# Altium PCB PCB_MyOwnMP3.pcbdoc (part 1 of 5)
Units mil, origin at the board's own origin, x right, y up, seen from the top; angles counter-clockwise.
Board outline 3605 x 4860 mil, 6 copper layers (Top Layer, Inner1, Inner2, Inner3, Inner4, Bottom Layer); 291 components, 261 nets, 1070 pads, 1658 vias.
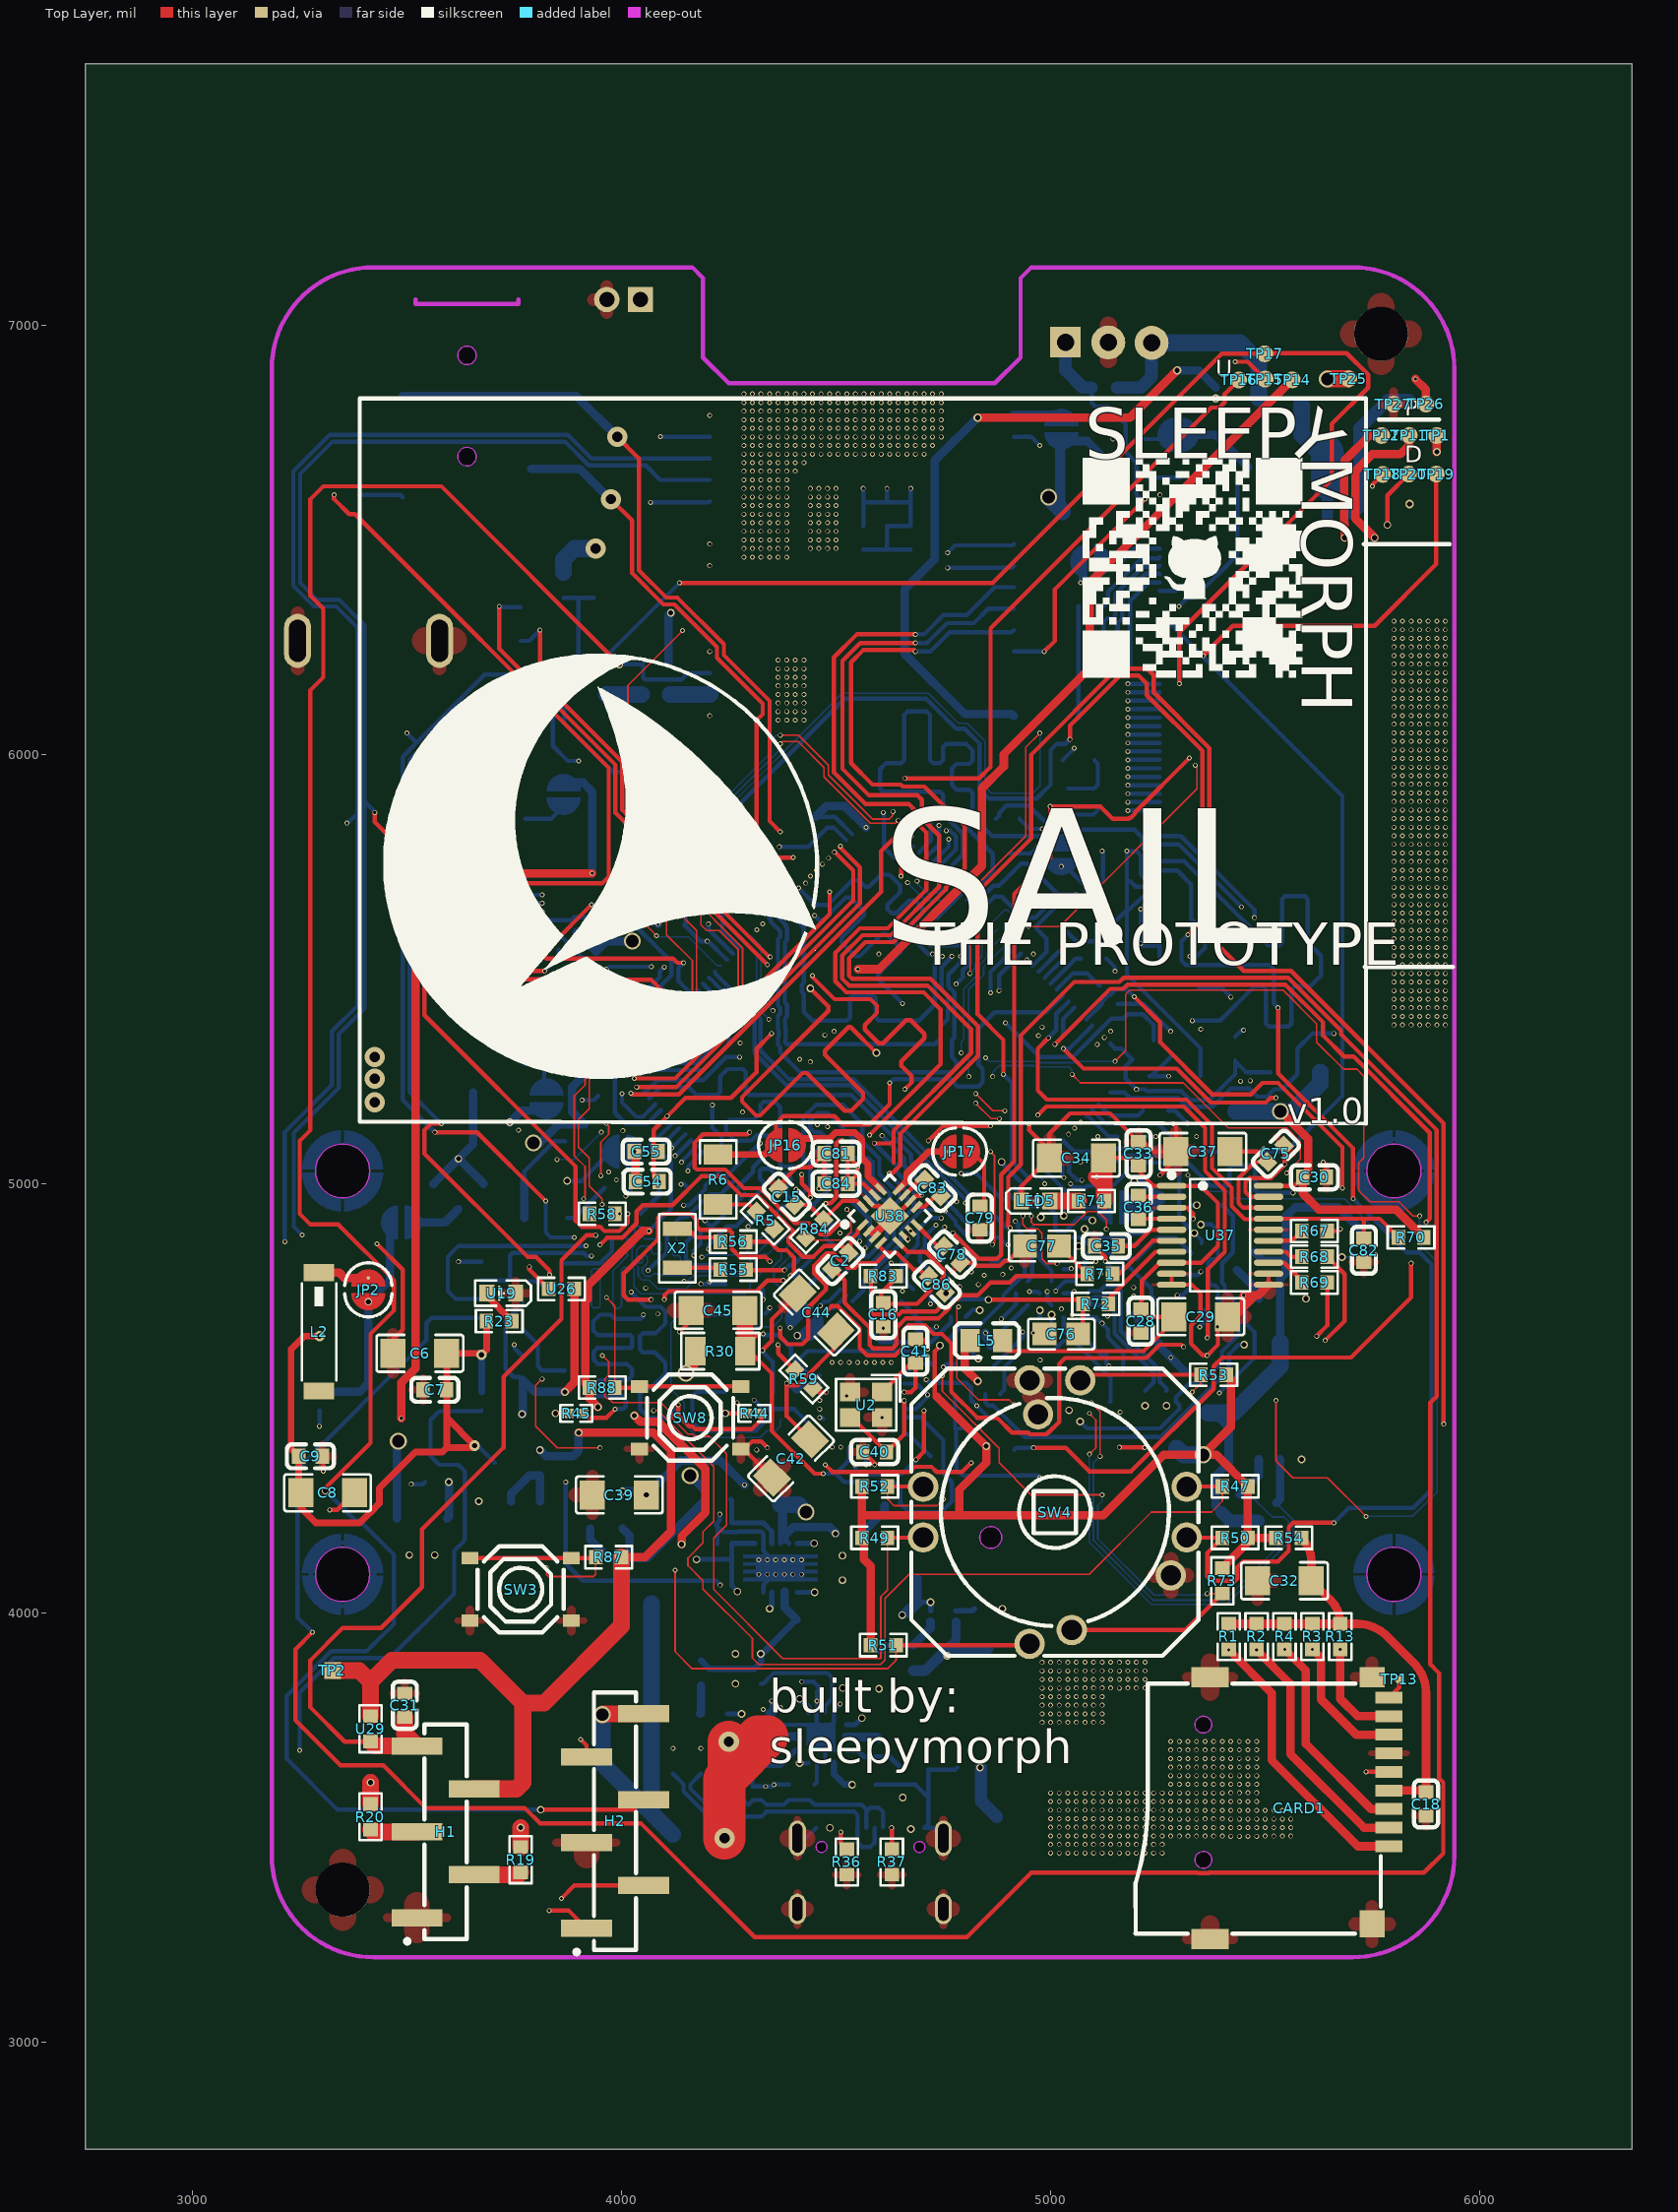
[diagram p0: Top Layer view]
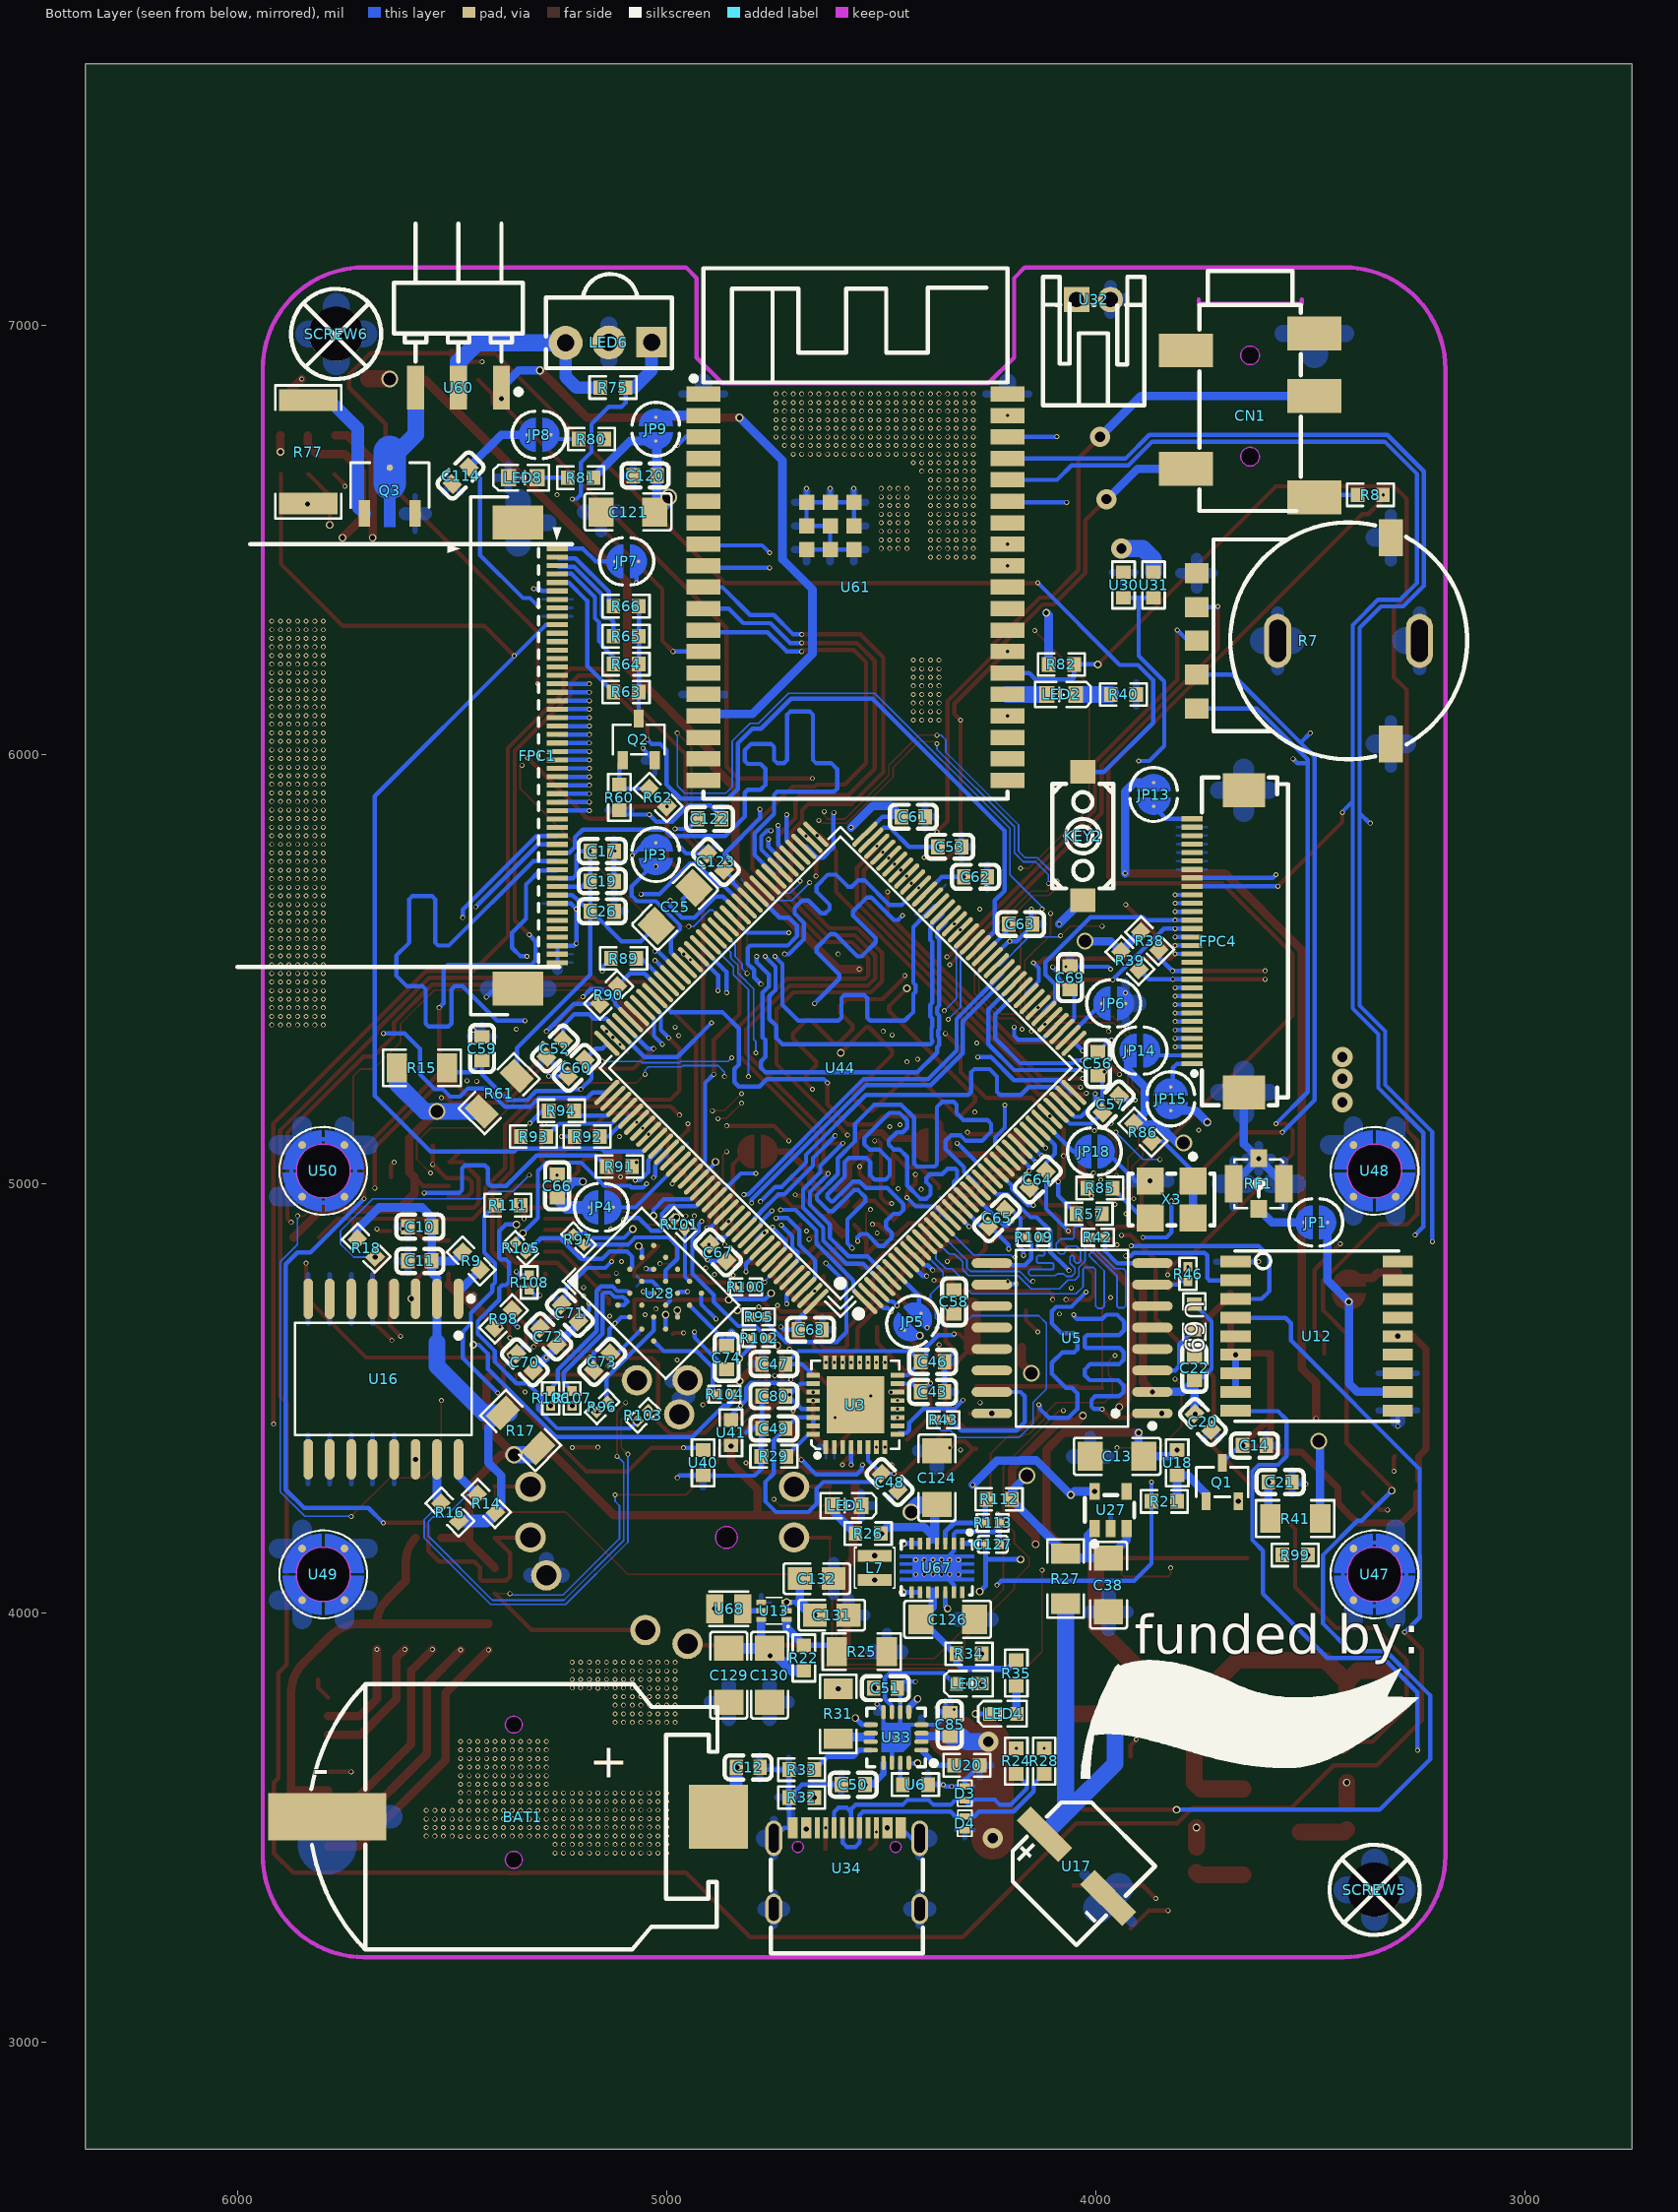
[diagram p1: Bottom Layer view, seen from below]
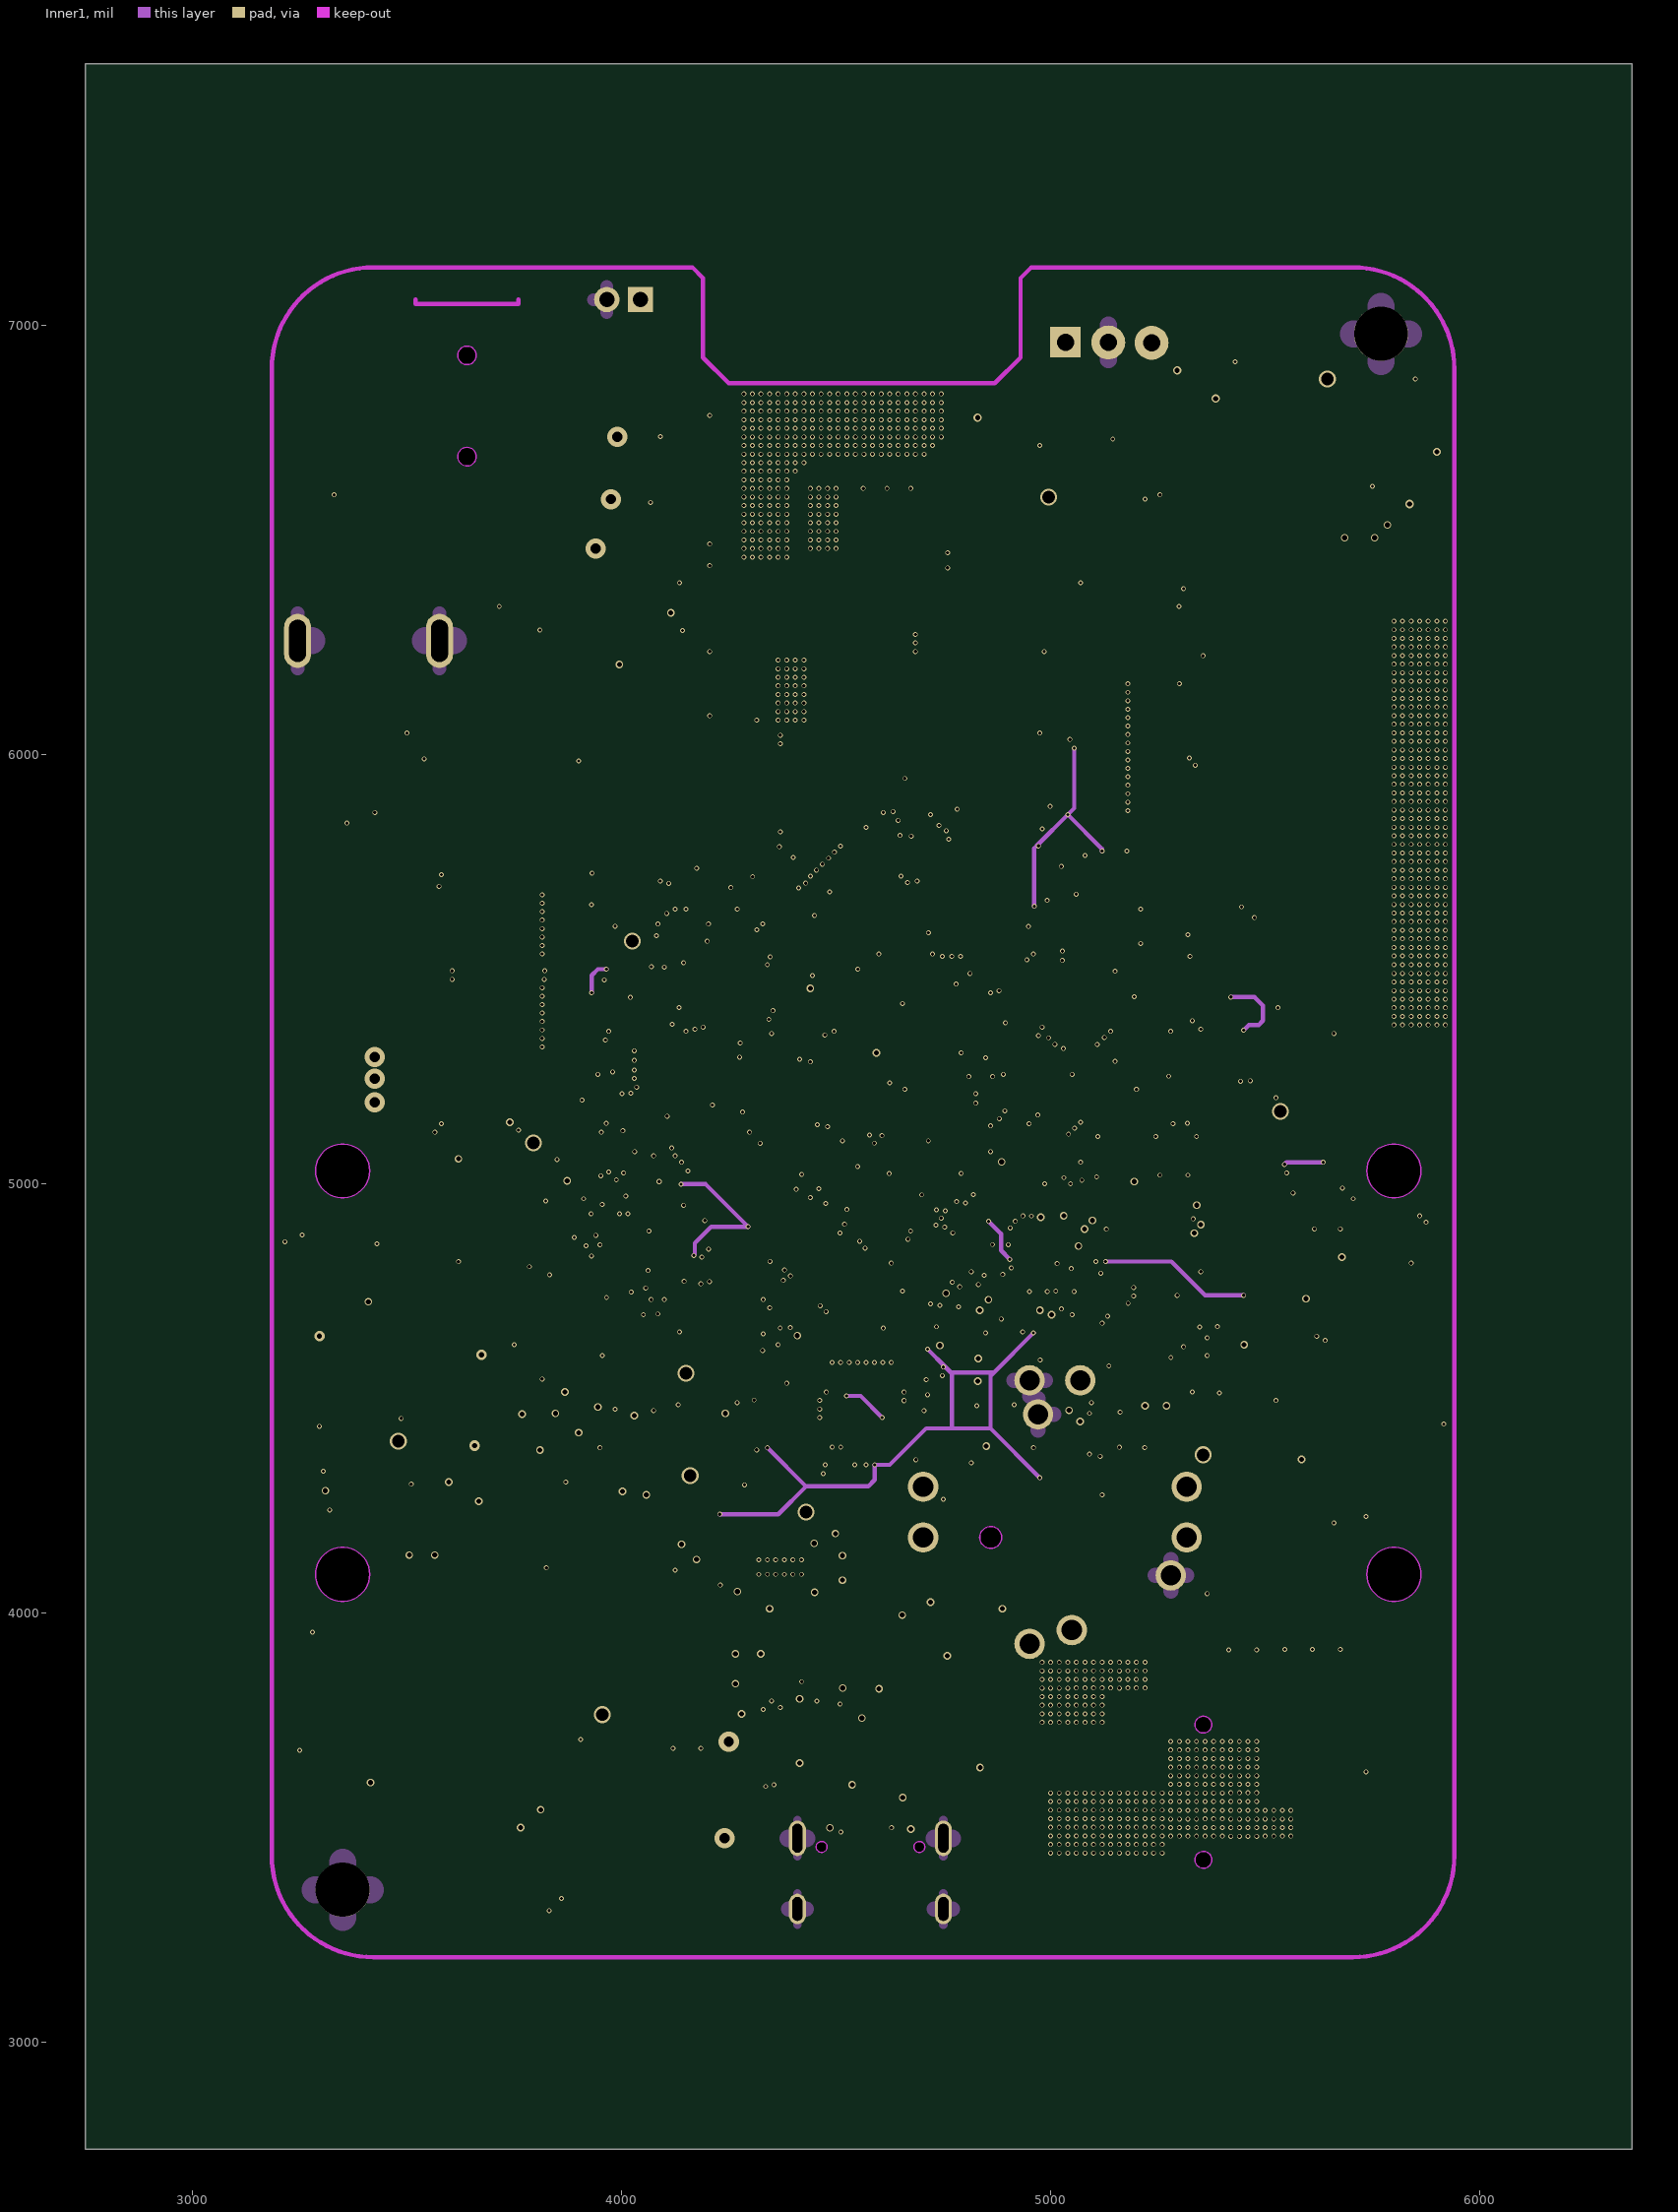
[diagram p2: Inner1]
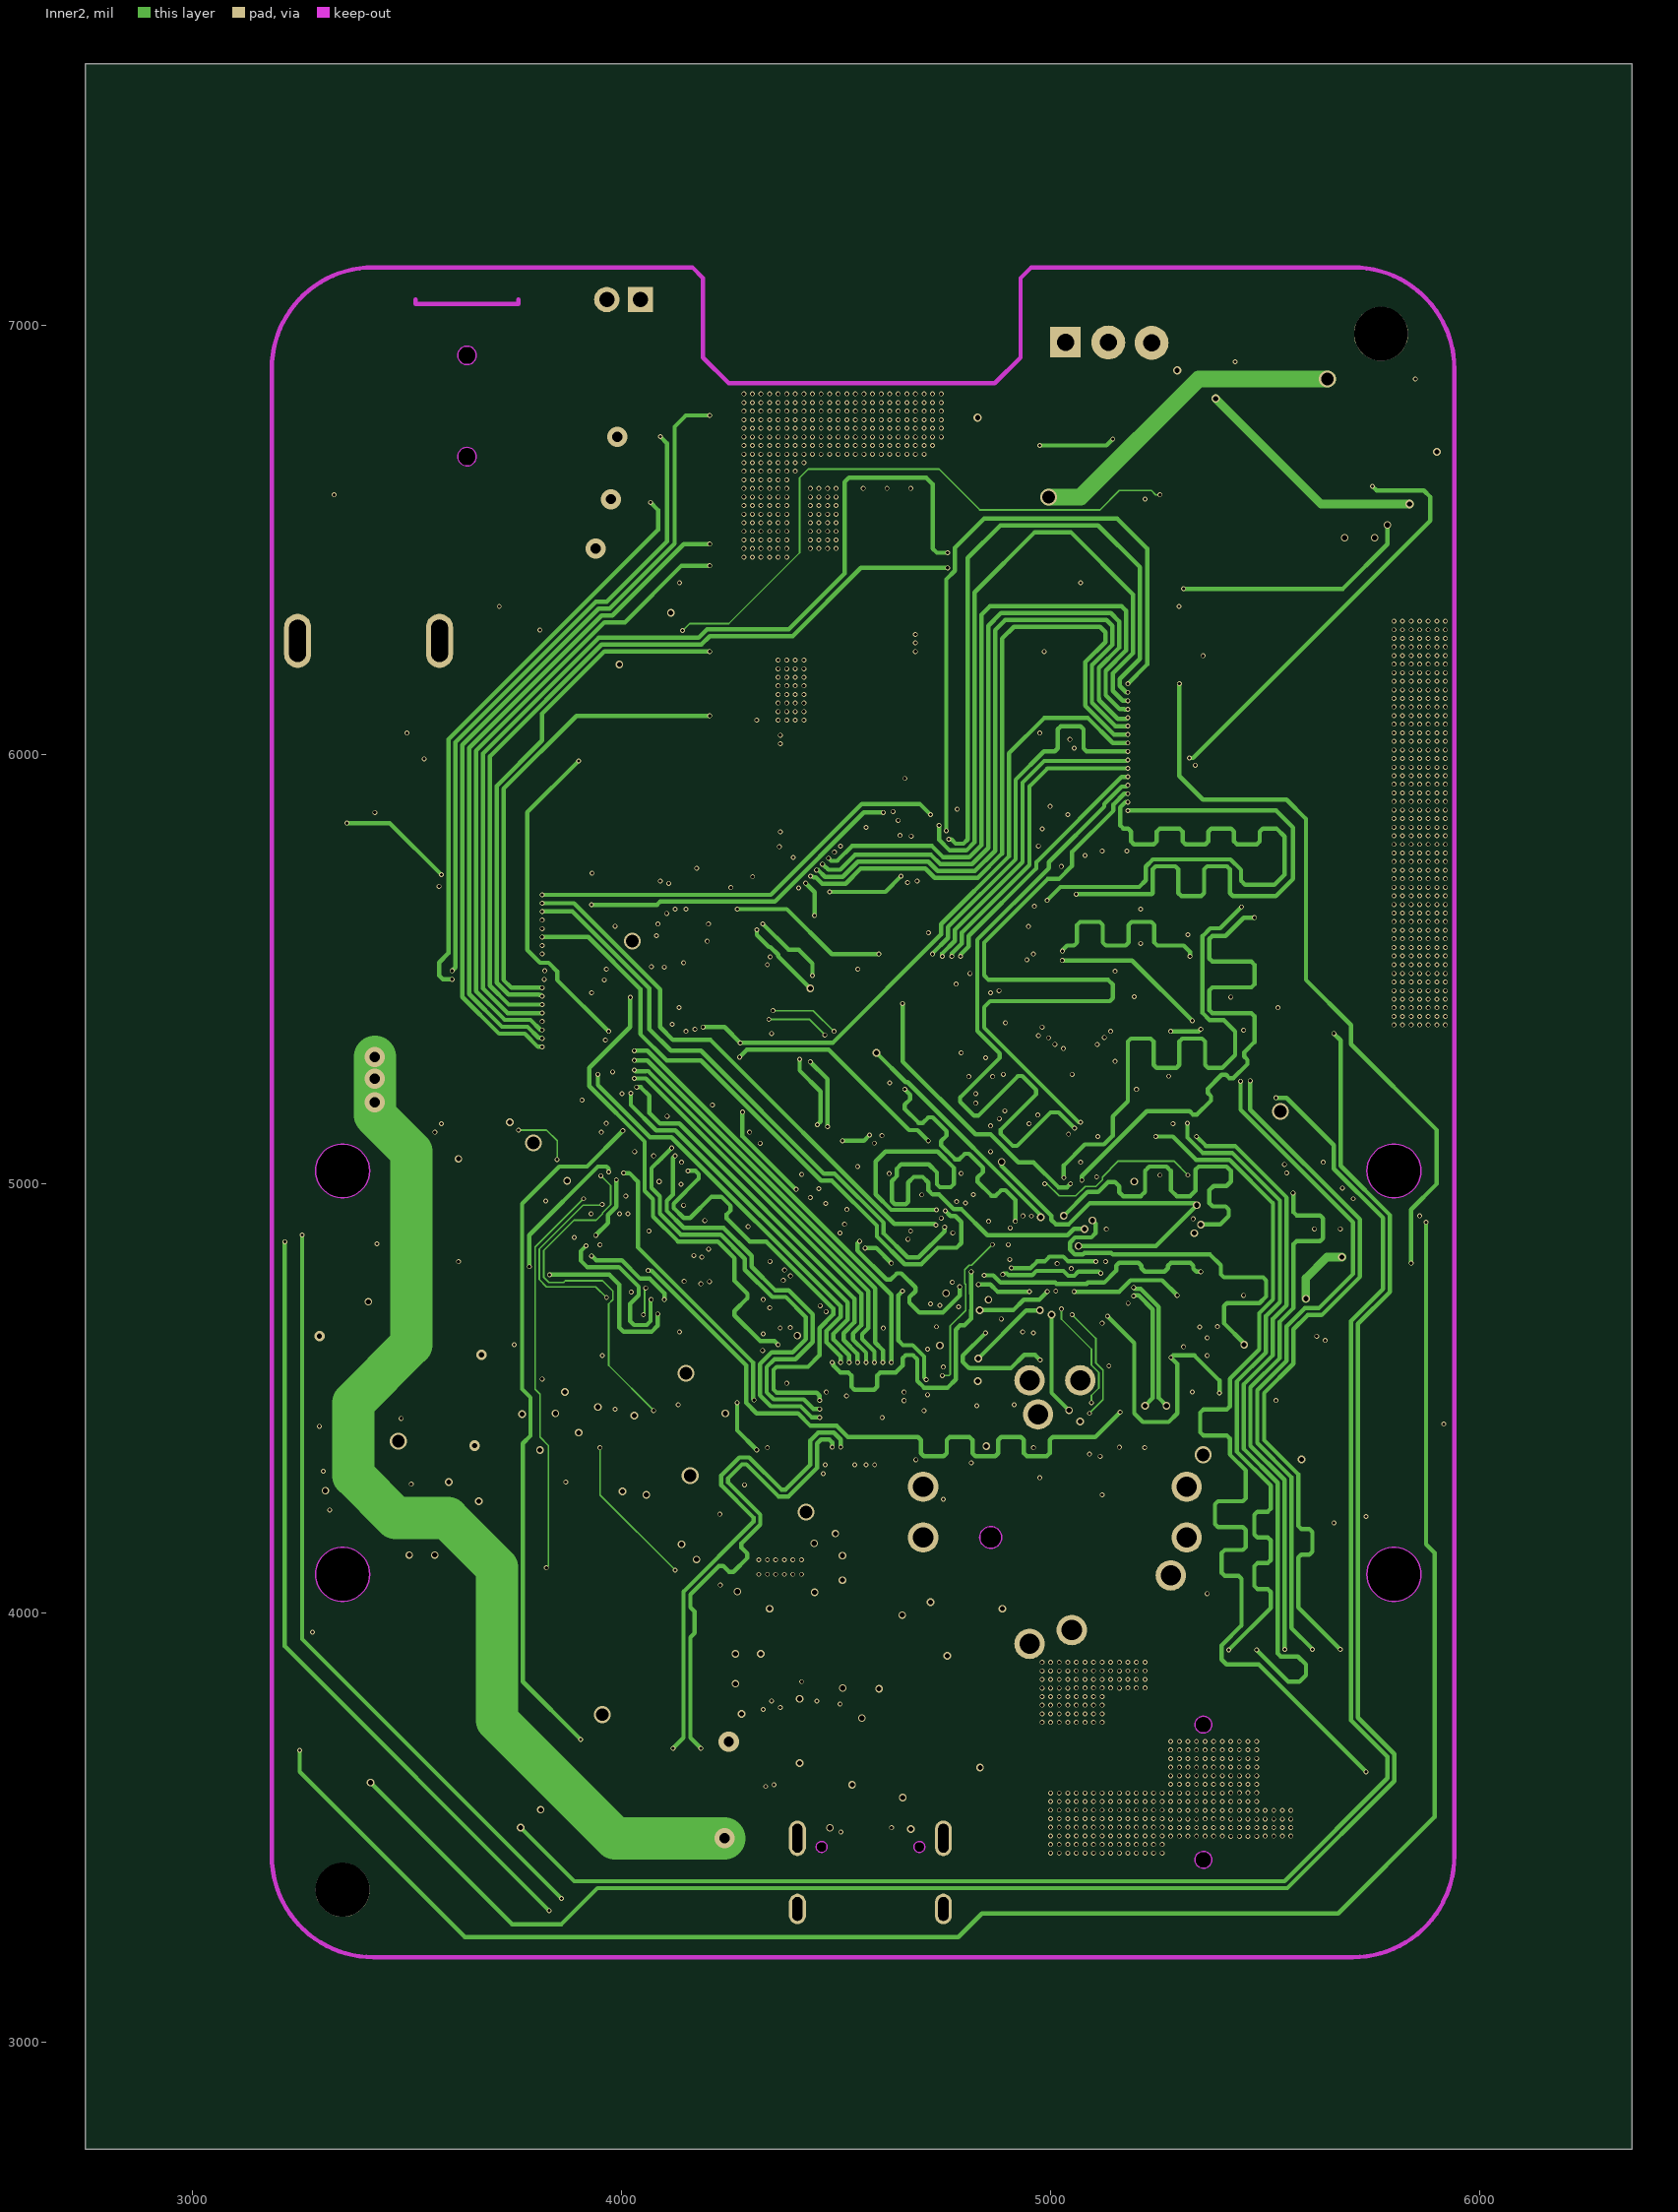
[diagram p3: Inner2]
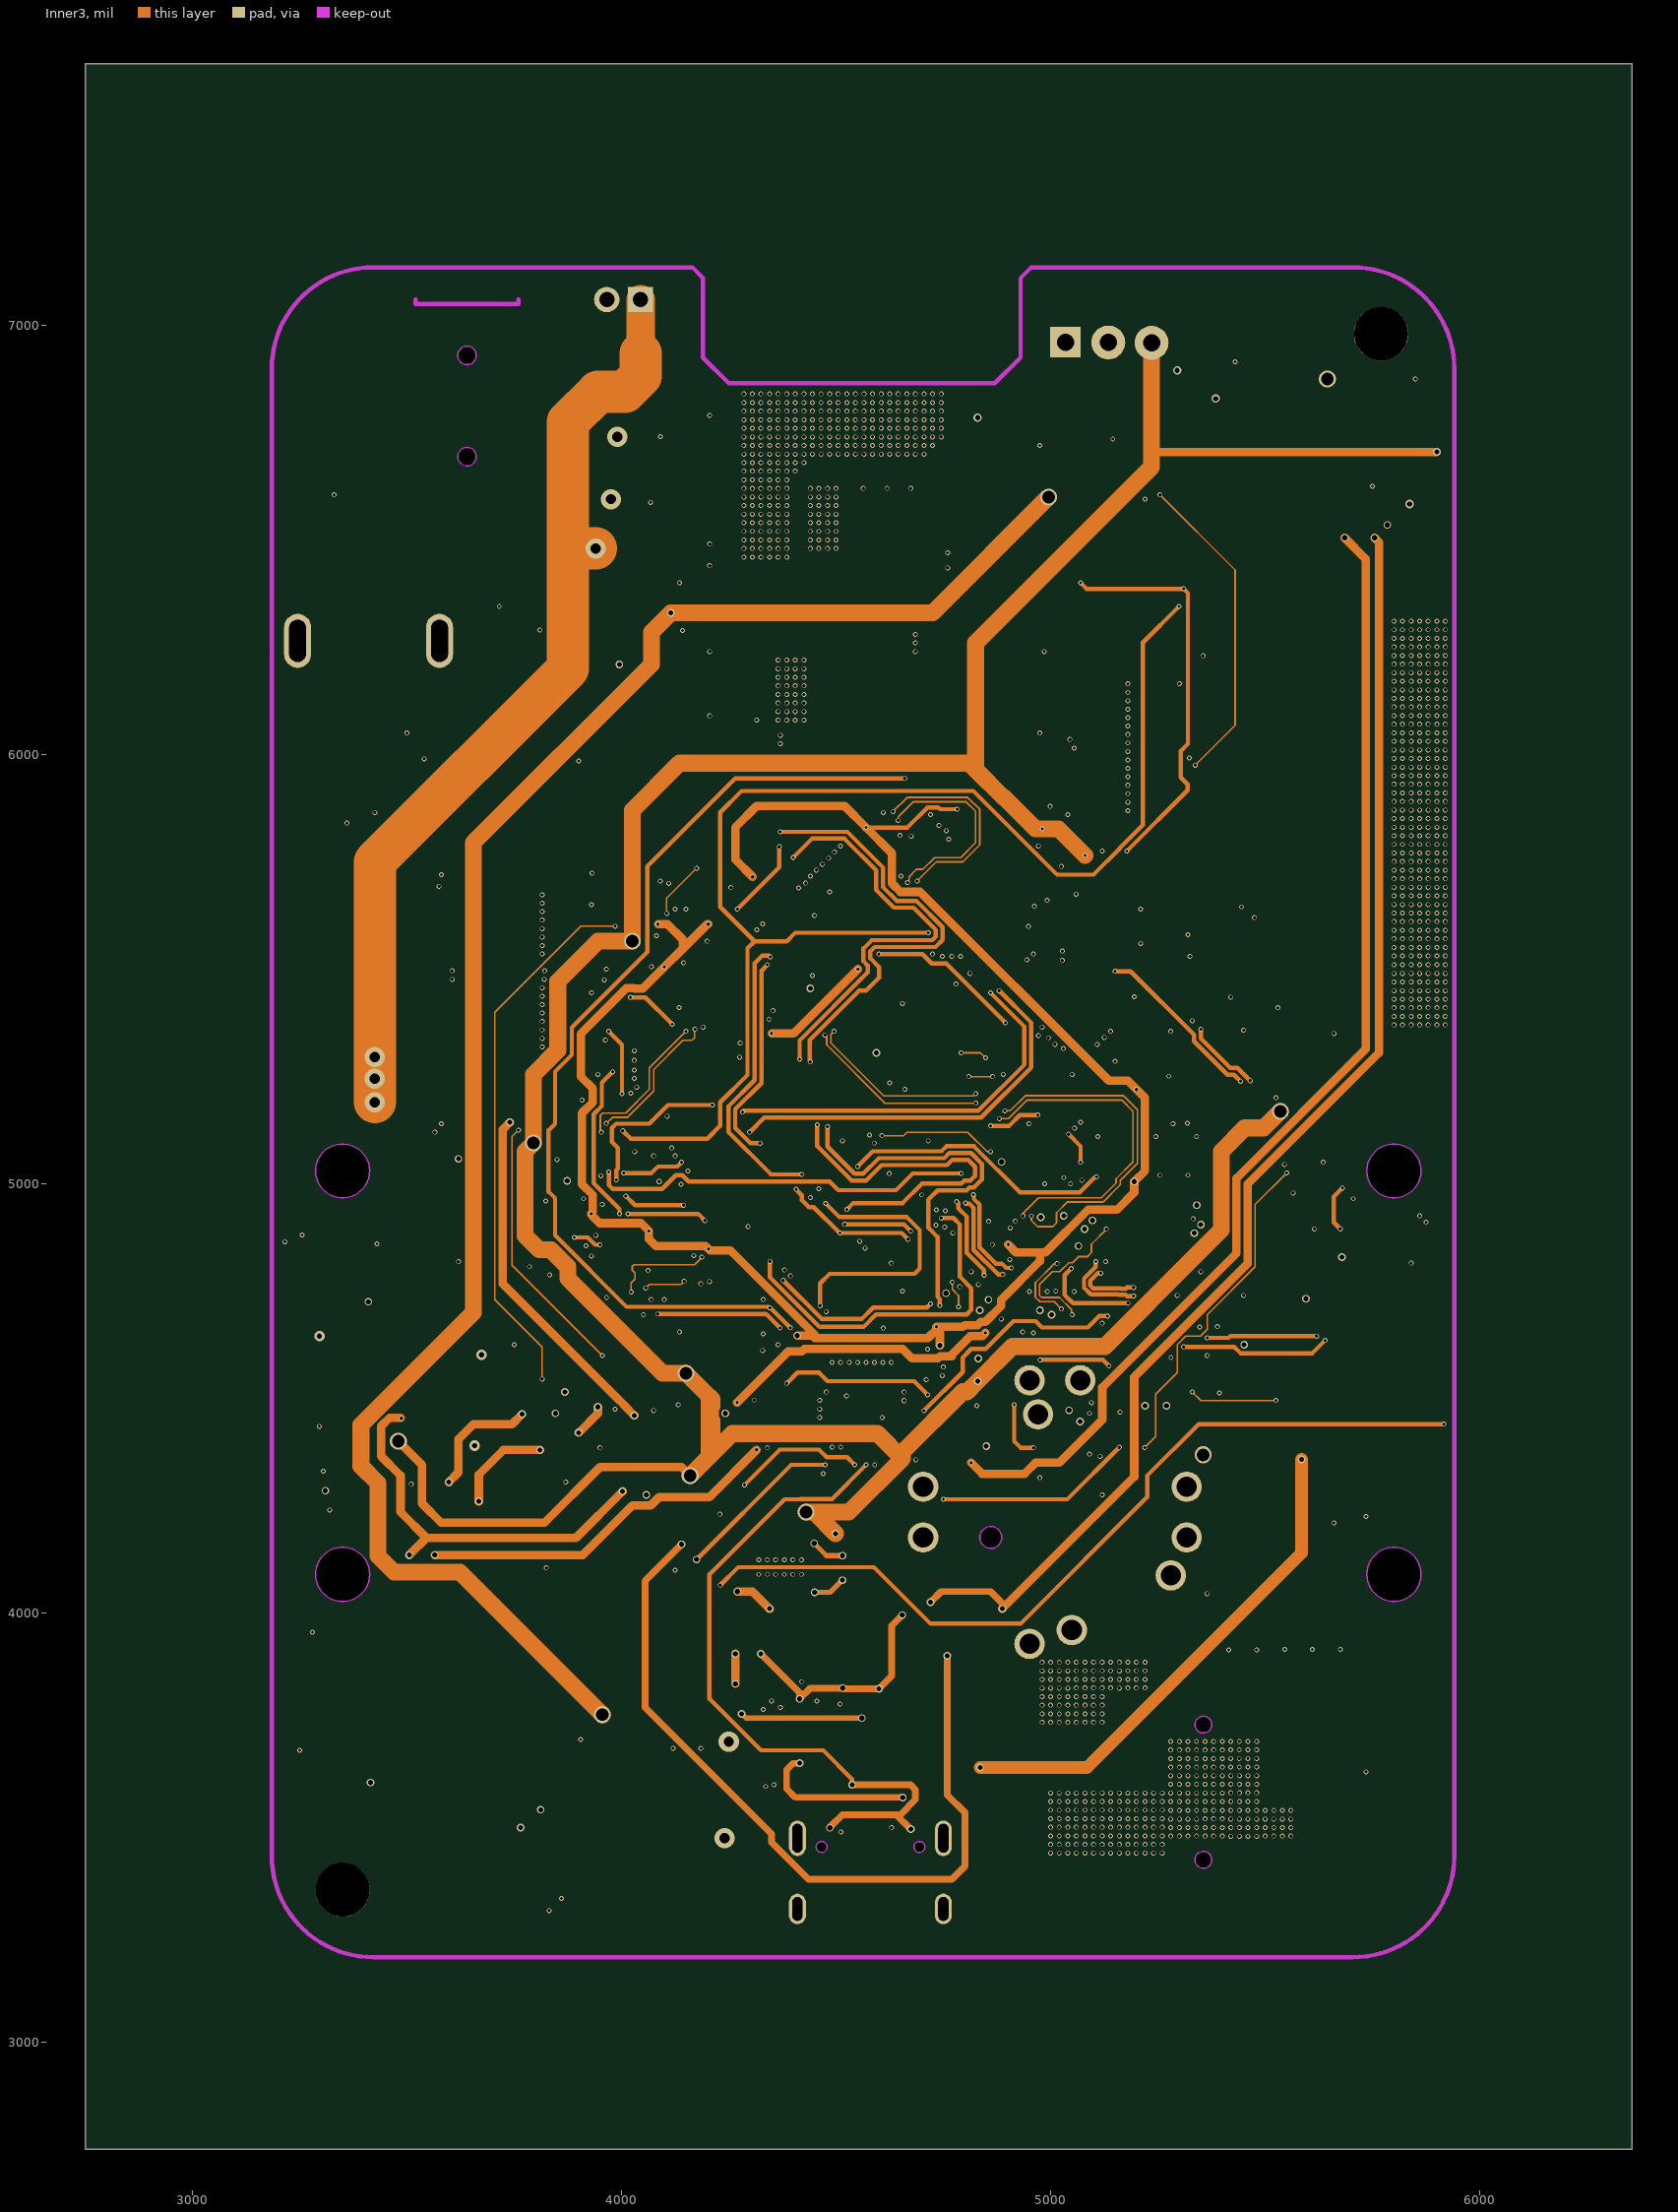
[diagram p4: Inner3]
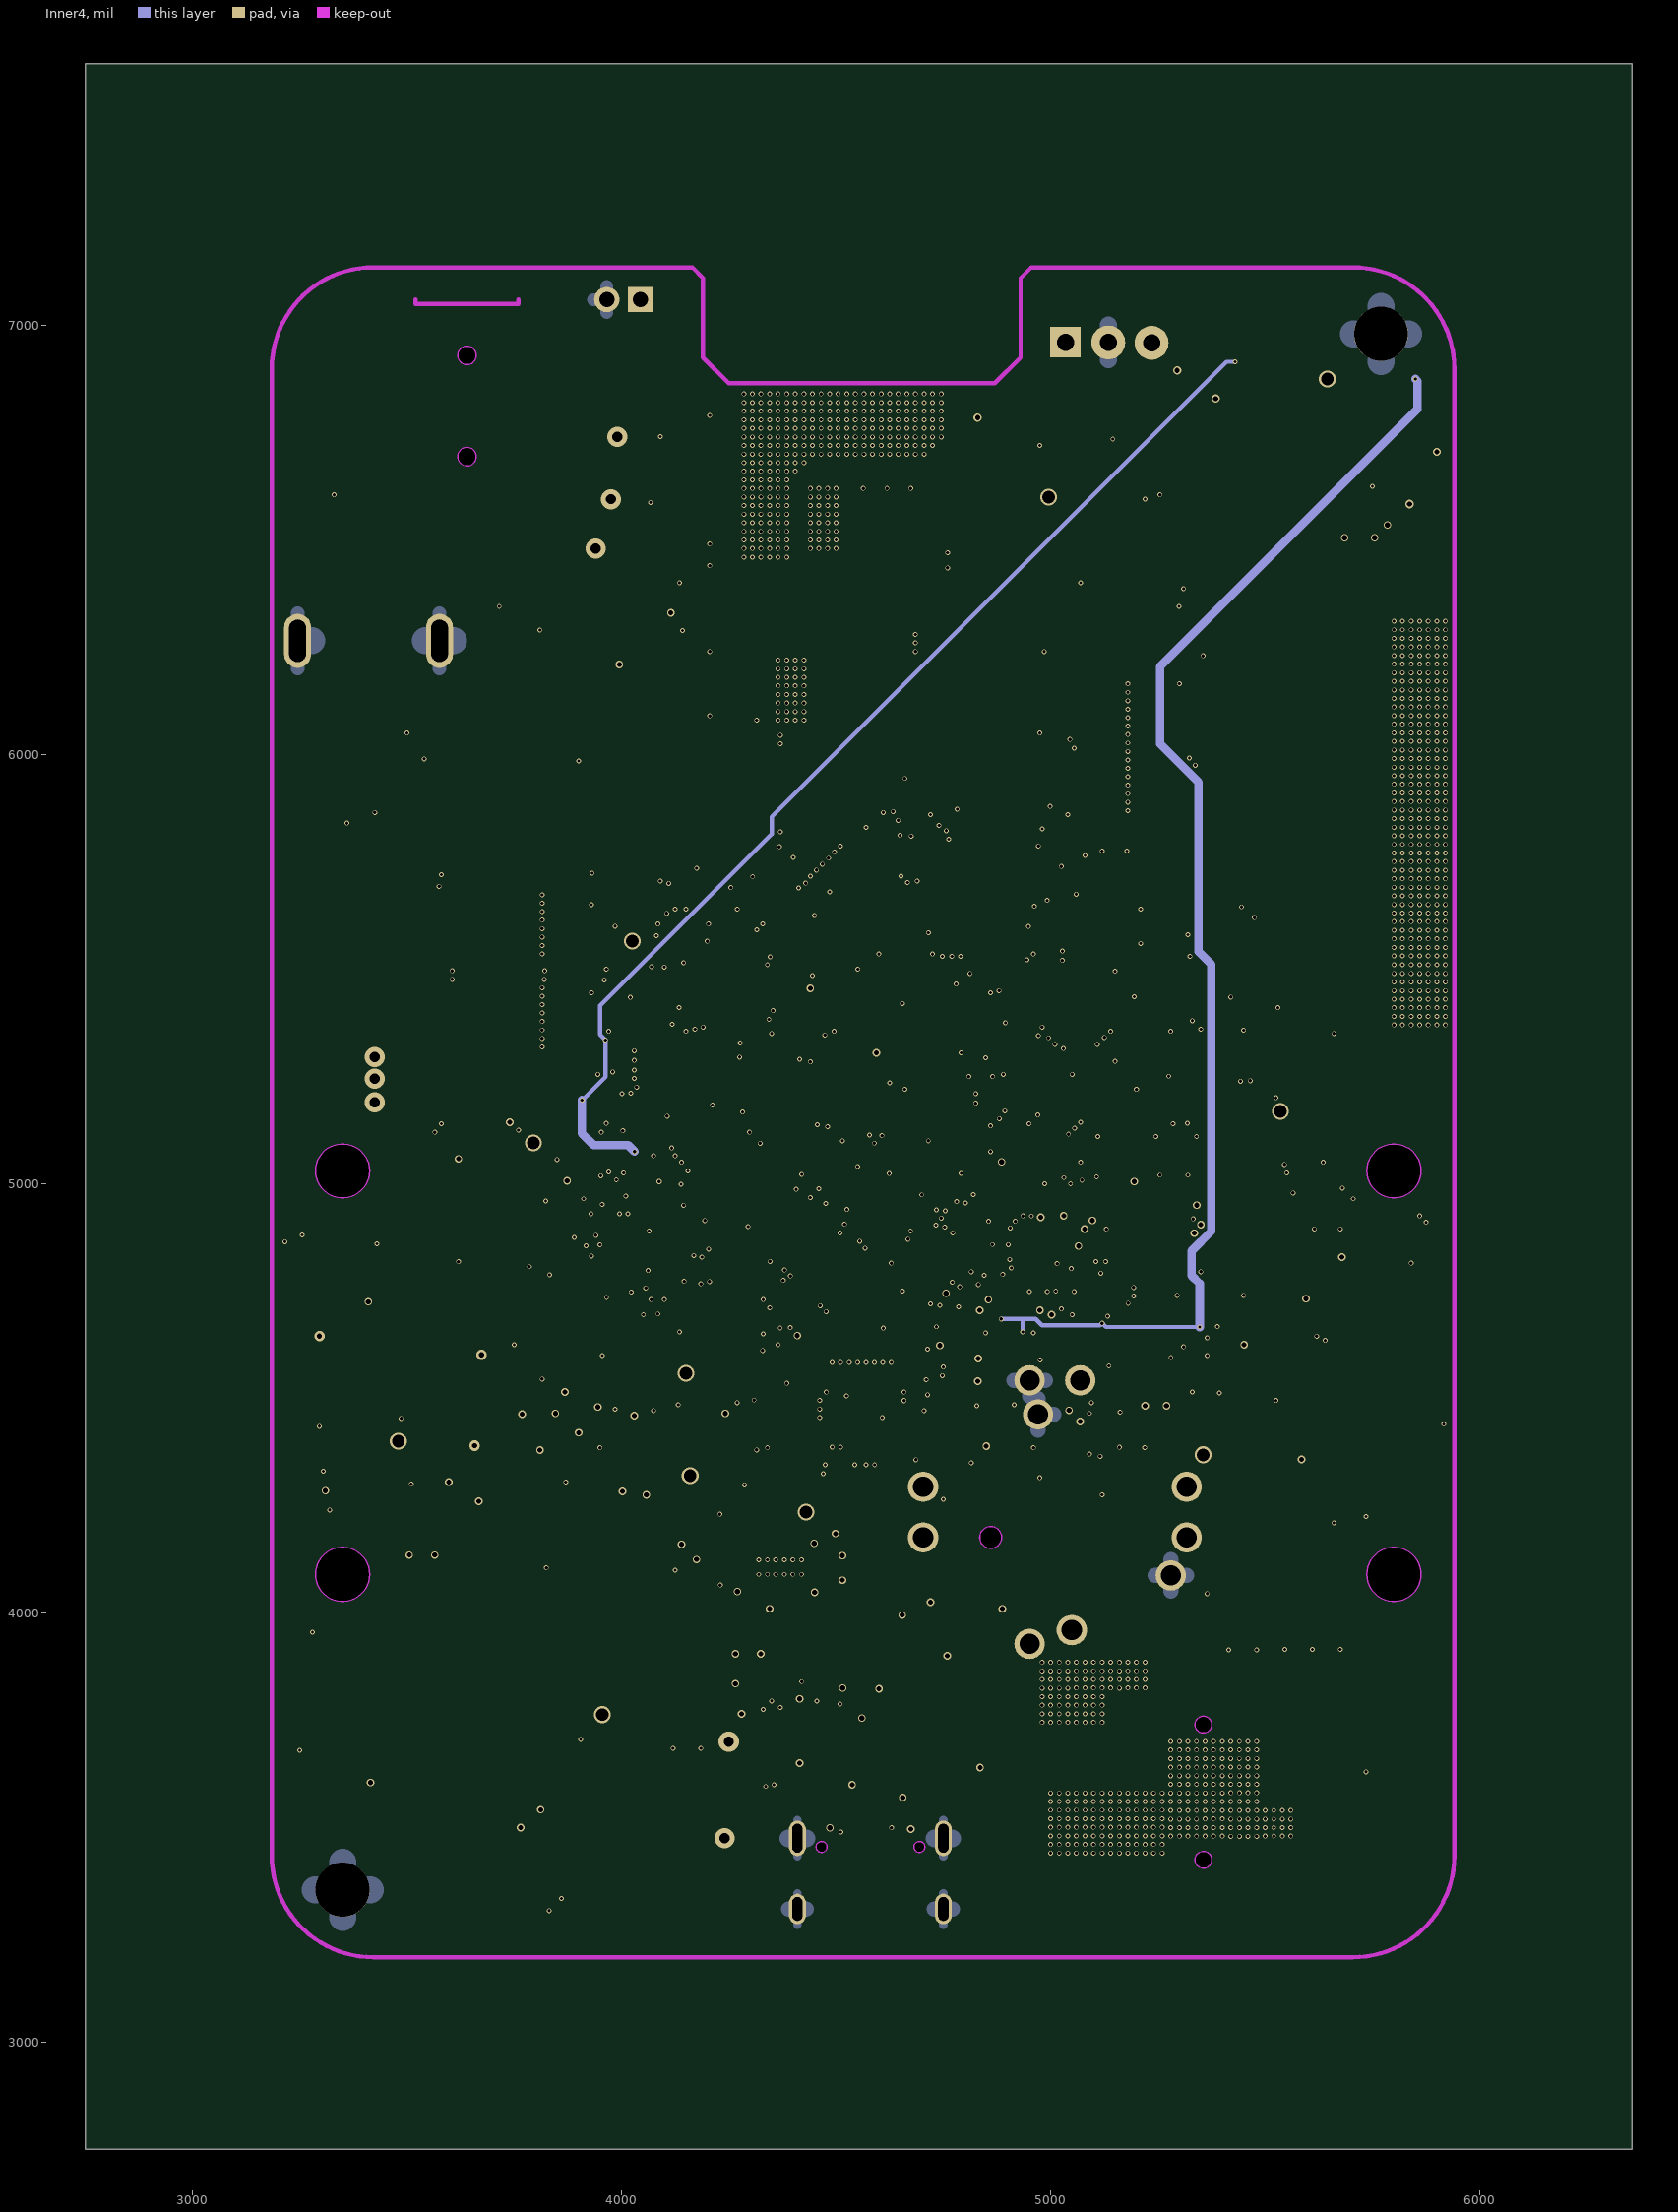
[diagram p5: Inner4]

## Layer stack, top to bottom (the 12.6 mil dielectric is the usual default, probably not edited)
Top Layer: signal copper (thickness not stored)
Dielectric: dielectric 12.6, FR-4, Dk 4.8
Inner1: signal copper (thickness not stored)
Dielectric: dielectric 12.6, FR-4, Dk 4.8
Inner2: signal copper (thickness not stored)
Dielectric: dielectric 12.6, FR-4, Dk 4.8
Inner3: signal copper (thickness not stored)
Dielectric: dielectric 12.6, FR-4, Dk 4.8
Inner4: signal copper (thickness not stored)
Dielectric: dielectric 12.6, FR-4, Dk 4.8
Bottom Layer: signal copper (thickness not stored)

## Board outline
6355,2750 2750,2750 2750,7610 6355,7610

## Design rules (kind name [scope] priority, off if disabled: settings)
BoardOutlineClearance Default [All] p0: genericclearance=10 ignorepadtopadclearanceinfootprint=FALSE except(0: Region-CutoutEdge Arc-SplitContinuation Track-SplitContinuation SMDPad-SplitContinuation THPad-SplitContinuation Via-SplitContinuation Fill-SplitContinuation Poly-SplitContinuation Region-SplitContinuation Text-SplitContinuation; 6: Track-OutlineEdge SMDPad-OutlineEdge THPad-OutlineEdge Via-OutlineEdge Fill-OutlineEdge Region-OutlineEdge Poly-OutlineEdge Text-OutlineEdge Track-CutoutEdge SMDPad-CutoutEdge THPad-CutoutEdge Via-CutoutEdge Fill-CutoutEdge)
Clearance Default [(InNet('GPS_VCC') OR InNet('B_B2') OR InNet('B_B1') OR InNet('PUSH_A') OR InNet('PUSH_B') OR InNet('ENC_B') OR InNet('PUSH_C') OR InNet('PUSH_D') OR InNet('ENC_A') OR InNet('CPP') OR InNet('CPN') OR InNet('OUTL') OR InNet('OUTR') OR InNet('XSMT') OR InNet('3V3_ANALOG') OR InNet('AMP_OUTL') OR InNet('VNEG') OR InNet('CAPP') OR InNet('CAPM') OR InNet('3V3_VDD') OR InNet('AMP_EN') OR InNet('PUSH_CTRL') OR InNet('VREF+') OR InNet('B_VIN') OR InNet('3V3_IPS') OR InNet('3V3_ESP32') OR InNet('VBAT') OR InNet('ESP_SDA') OR InNet('ESP_SCL') OR InNet('GNDA') OR InNet('B+') OR InNet('3V3_PHY') OR InNet('1V8_PHY') OR InNet('+5V') OR InNet('1V8_VCCQ') OR InNet('1V8_VDD') OR InNet('RTC_VCC') OR InNet('VDDA') OR InNet('VCAP') OR InNet('GND') OR InNet('ESP32_EN') OR InNet('GPS_TG') OR InNet('IPS_PWM') OR InNet('CC_CSN') OR InNet('CC_GDO0') OR InNet('CC_GDO2') OR InNet('CC_MISO') OR InNet('CC_MOSI') OR InNet('CC_SCK') OR InNet('NFC_CS') OR InNet('NFC_IRQ') OR InNet('CS4') OR InNet('CS3') OR InNet('CS2') OR InNet('CS1') OR InNet('ESP_CS') OR InNet('ESP_SCK') OR InNet('ESP_MISO') OR InNet('ESP_MOSI') OR InNet('FS_A') OR InNet('SCK_A') OR InNet('SD_A') OR InNet('IR_RX') OR InNet('IR_TX') OR InNet('RXD0') OR InNet('TXD0') OR InNet('LED7_2') OR InNet('IPS_RST') OR InNet('FMC_D15') OR InNet('FMC_D14') OR InNet('FMC_D13') OR InNet('FMC_D12') OR InNet('FMC_D11') OR InNet('FMC_D10') OR InNet('FMC_D9') OR InNet('FMC_D8') OR InNet('FMC_D7') OR InNet('FMC_D6') OR InNet('FMC_D5') OR InNet('FMC_D4') OR InNet('FMC_D3') OR InNet('FMC_D2') OR InNet('FMC_D1') OR InNet('FMC_D0') OR InNet('FMC_NOE') OR InNet('FMC_NWE') OR InNet('FMC_A16') OR InNet('FMC_NE1') OR InNet('IPS_TE') OR InNet('V_OUTR') OR InNet('V_OUTL') OR InNet('ULPI.D0') OR InNet('ULPI.D1') OR InNet('ULPI.D2') OR InNet('ULPI.D3') OR InNet('ULPI.D4') OR InNet('ULPI.D5') OR InNet('ULPI.D6') OR InNet('ULPI.D7') OR InNet('ULPI.STP') OR InNet('ULPI.DIR') OR InNet('ULPI.NXT') OR InNet('ULPI.RST') OR InNet('USB_DM') OR InNet('USB_DP') OR InNet('USB_5V') OR InNet('NRST') OR InNet('3V3_QSPI') OR InNet('GPS_TXD') OR InNet('GPS_RXD') OR InNet('GPS_PPS') OR InNet('GPS_RST') OR InNet('VSSQ') OR InNet('RESET#') OR InNet('DQ2') OR InNet('DAC_DIN') OR InNet('QSPI_IO0') OR InNet('QSPI_IO1') OR InNet('QSPI_IO2') OR InNet('QSPI_IO3') OR InNet('QSPI_CLK') OR InNet('DQ3') OR InNet('DETECT') OR InNet('DQ0') OR InNet('DQ1') OR InNet('OSC-IN') OR InNet('OSC-OUT') OR InNet('B_ADC') OR InNet('RWDS') OR InNet('DAC_BCK') OR InNet('ULPI.CLK') OR InNet('CK') OR InNet('CK#') OR InNet('RTC_SCL') OR InNet('RTC_SDA') OR InNet('DQ4') OR InNet('DQ5') OR InNet('CS#') OR InNet('AMP_G0') OR InNet('AMP_G1') OR InNet('DAC_LRCK') OR InNet('SWDIO') OR InNet('SWCLK') OR InNet('RTC_INT') OR InNet('DQ6') OR InNet('DQ7') OR InNet('QSPI_NCS') OR InNet('AMP_OUTR') OR InNet('SD_DATA0') OR InNet('SD_DATA1') OR InNet('SD_CMD') OR InNet('SD_CLK') OR InNet('SD_DATA3') OR InNet('SD_DATA2') OR InNet('3V3_SD') OR InNet('OSC32_OUT') OR InNet('OSC32_IN') OR InNet('IO0') OR InNet('$3N80') OR InNet('$1N36') OR InNet('$3N60') OR InNet('$2N6') OR InNet('$2N3') OR InNet('$3N83') OR InNet('$3N76') OR InNet('$3N81') OR InNet('$2N34') OR InNet('$2N37') OR InNet('$3N4539') OR InNet('$3N4538') OR InNet('$3N4537') OR InNet('$1N3524') OR InNet('$1N23') OR InNet('$1N3525') OR InNet('$1N3616') OR InNet('$1N3621') OR InNet('$1N85') OR InNet('$3N4388') OR InNet('$3N4532') OR InNet('$3N4531') OR InNet('$3N4373') OR InNet('$3N4372') OR InNet('$3N4431') OR InNet('$3N180') OR InNet('$3N4420') OR InNet('$3N84') OR InNet('$1N3521') OR InNet('$1N3479') OR InNet('$1N3480') OR InNet('$1N3543') OR InNet('$1N16') OR InNet('$2N65') OR InNet('$2N1552') OR InNet('$2N1556') OR InNet('$2N1557') OR InNet('$2N1558') OR InNet('$1N3474') OR InNet('$1N3472') OR InNet('$1N3471') OR InNet('$1N3478') OR InNet('$1N3475') OR InNet('3V3') OR InNet('$1N68') OR InNet('$1N69') OR InNet('$2N62') OR InNet('$3N4395') OR InNet('$3N4392') OR InNet('$3N21') OR InNet('$3N4391') OR InNet('$3N4390') OR InNet('$3N4389') OR InNet('$3N4371') OR InNet('$3N4370') OR InNet('$3N4369') OR InNet('$3N63') OR InNet('$3N64') OR InNet('$3N4480') OR InNet('$3N161') OR InNet('$3N4409') OR InNet('$3N4408') OR InNet('$1N3651') OR InNet('$1N183') OR InNet('$1N186') OR InNet('$1N187') OR InNet('$1N189') OR InNet('$1N190') OR InNet('$1N188') OR InNet('$1N3572') OR InNet('$1N3571') OR InNet('$1N3570') OR InNet('$1N3569') OR InNet('$1N3568') OR InNet('$1N3567') OR InNet('$1N3566') OR InNet('$1N3562') OR InNet('$1N3563') OR InNet('$1N3564') OR InNet('$1N3565') OR InNet('$2N64') OR InNet('$1N42') OR InNet('$2N1532') OR InNet('$1N87') OR InNet('$1N3624') OR InNet('$1N3542') OR InNet('$3N220') OR InNet('$2N1551') OR InNet('$2N1555') OR InNet('$2N16') OR InNet('$2N1545') OR InNet('$2N1546') OR InNet('$1N185') OR InNet('$1N3573') OR InNet('$1N3473') OR InNet('$1N13209') OR InNet('$1N12583') OR InNet('$1N12689') OR InNet('$1N12675') OR InNet('$1N12314') OR InNet('$3N18001') OR InNet('$1N24923') OR InNet('$1N3476'))] p1: gap=7 ignorepadtopadclearanceinfootprint=FALSE except(0: Region-Region; 6: Track-Track Track-SMDPad SMDPad-SMDPad Track-THPad SMDPad-THPad THPad-THPad Track-Via SMDPad-Via THPad-Via Via-Via Track-Fill SMDPad-Fill THPad-Fill Via-Fill Fill-Fill Track-Region SMDPad-Region THPad-Region Via-Region Fill-Region Track-Poly SMDPad-Poly THPad-Poly Via-Poly Fill-Poly Region-Poly Poly-Poly Track-Text SMDPad-Text THPad-Text Via-Text Fill-Text Region-Text Poly-Text Text-Text Track-Sheet SMDPad-Sheet THPad-Sheet Via-Sheet Fill-Sheet Region-Sheet Poly-Sheet Text-Sheet Track-Hole SMDPad-Hole THPad-Hole Via-Hole Fill-Hole Region-Hole Poly-Hole Text-Hole Sheet-Hole)
DiffPairsRouting differentialPair [All] p1: maxuncoupledlength=11.811 minlimit=3.937 maxlimit=3.937 mostfreqgap=3.937 toplayer_minwidth=3.937 toplayer_prefwidth=4.7244 toplayer_maxwidth=100 bottomlayer_minwidth=3.937 bottomlayer_prefwidth=4.7244 bottomlayer_maxwidth=100 midlayer1_minwidth=3.937 midlayer1_prefwidth=4.7244 midlayer1_maxwidth=100 midlayer2_minwidth=3.937 midlayer2_prefwidth=4.7244 midlayer2_maxwidth=100 midlayer3_minwidth=3.937 midlayer3_prefwidth=4.7244 midlayer3_maxwidth=100 midlayer4_minwidth=3.937 midlayer4_prefwidth=4.7244 midlayer4_maxwidth=100
PasteMaskExpansion Common [All] p1: expansion=0
PlaneConnect Default [All] p1: planeconnectstyle=Relief reliefexpansion=20 reliefentries=4 reliefconductorwidth=0 reliefairgap=10
PolygonConnect Default [All] p1: connectstyle=Relief reliefentries=4 reliefconductorwidth=0 polygonreliefangle="90 Angle" airgapwidth=10
RoutingVias Default [All] p1: viastyle="Through Hole" holewidth=7.48 minholewidth=7.48 maxholewidth=2362 width=11.417 minwidth=11.417 maxwidth=3938
SolderMaskExpansion Common [All] p1: useseparateexpansions=TRUE expansion=2 expansionbottom=2
Width Default [All] p1: maxlimit=1000 minlimit=4 preferedwidth=10
Width IO1 [All] p1: maxlimit=4 minlimit=4 preferedwidth=4
Width IO2 [All] p1: maxlimit=4 minlimit=4 preferedwidth=4

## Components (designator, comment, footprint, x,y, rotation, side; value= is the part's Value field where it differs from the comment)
BAT1 "BS-CR2032-8" BAT-SMD_BS-CR2032-8 5335,3525 r180 bottom
C2 "1uF" C0603 4510,4820 r225 top
C6 "10uF" C1206 3530,4605 r180 top
C7 "100nF" C0603 3565,4520 r180 top
C8 "10uF" C1206 3315,4280 r180 top
C9 "100nF" C0603 3275,4365 r0 top
C10 "1uF" C0603 5575,4900 r180 bottom
C11 "100nF" C0603 5575,4820 r0 bottom
C12 "100nF" C0603 4810,3640 r180 bottom
C13 "10uF" C1206 3950,4365 r180 bottom
C14 "1uF" C0603 3630,4390 r0 bottom
C15 "100pF" C0603 4385,4970 r315 top
C16 "100pF" C0603 4610,4695 r270 top
C17 "100nF" C0603 5150,5775 r180 bottom
C18 "100nF" C0603 5875,3555 r90 top
C19 "100nF" C0603 5150,5705 r180 bottom
C20 "100nF" C0603 3750,4445 r225 bottom
C21 "100nF" C0603 3570,4305 r180 bottom
C22 "4.7uF" C0603 3770,4570 r270 bottom
C25 "10uF" C1206 4980,5645 r315 bottom
C26 "100nF" C0603 5150,5635 r180 bottom
C28 "100nF" C0603 5210,4680 r90 top
C29 "10uF" C1206 5350,4690 r0 top
C30 "100nF" C0603 5615,5015 r0 top
C31 "100nF" C0603 3495,3785 r90 top
C32 "10uF" C1206 5545,4075 r0 top
C33 "100nF" C0603 5205,5070 r270 top
C34 "10uF" C1206 5060,5060 r180 top
C35 "2.2uF" C0603 5130,4855 r180 top
C36 "2.2uF" C0603 5205,4945 r270 top
C37 "10uF" C1206 5355,5075 r180 top
C38 "10uF" C1206 3970,4065 r90 bottom
C39 "10uF" C1206 3995,4275 r0 top
C40 "20pF" C0603 4590,4375 r0 top
C41 "20pF" C0603 4685,4610 r90 top
C42 "10uF" C1206 4395,4360 r45 top
C43 "100nF" C0603 4380,4515 r0 bottom
C44 "10uF" C1206 4455,4700 r315 top
C45 "10uF" C1206 4225,4705 r0 top
C46 "100nF" C0603 4380,4585 r180 bottom
C47 "100nF" C0603 4750,4580 r0 bottom
C48 "100nF" C0603 4480,4305 r225 bottom
C49 "100nF" C0603 4750,4430 r0 bottom
C50 "1uF" C0603 4565,3600 r180 bottom
C51 "4.7uF" C0603 4490,3825 r0 bottom
C52 "2.2uF" C0603 5260,5315 r135 bottom
C53 "2.2uF" C0603 4340,5785 r0 bottom
C54 "1uF" C0603 4060,5005 r0 top
C55 "100nF" C0603 4057.44,5075 r180 top
C56 "100nF" C0603 3995,5280 r90 bottom
C57 "1uF" C0603 3965,5185 r315 bottom
C58 "1uF" C0603 4330,4725 r270 bottom
C59 "4.7uF" C0603 5430,5315 r270 bottom
C60 "100nF" C0603 5210,5270 r315 bottom
C61 "100nF" C0603 4425,5855 r180 bottom
C62 "100nF" C0603 4280,5715 r180 bottom
C63 "100nF" C0603 4175,5605 r180 bottom
C64 "100nF" C0603 4135,5010 r315 bottom
C65 "100nF" C0603 4230,4920 r135 bottom
C66 "100nF" C0603 5255,4995 r90 bottom
C67 "100nF" C0603 4880,4840 r225 bottom
C68 "100nF" C0603 4665,4660 r180 bottom
C69 "100nF" C0603 4060,5480 r90 bottom
C70 "2.2uF" C0603 5330.28,4583.97 r225 bottom
C71 "100nF" C0603 5225.28,4698.97 r45 bottom
C72 "100nF" C0603 5275.28,4643.97 r45 bottom
C73 "100nF" C0603 5150,4585 r315 bottom
C74 "100nF" C0603 4860,4595 r270 bottom
C75 "100nF" C0603 5525,5070 r225 top
C76 "2.2nF" C0805 5025,4650 r0 top
C77 "2.2nF" C0805 4980,4855 r0 top
C78 "1uF" C0603 4770,4835 r135 top
C79 "2.2uF" C0603 4835,4920 r90 top
C80 "100nF" C0603 4750,4505 r180 bottom
C81 "2.2uF" C0603 4500,5070 r0 top
C82 "100nF" C0603 5730,4845 r270 top
C83 "1uF" C0603 4725,4990 r135 top
C84 "100nF" C0603 4500,5000 r0 top
C85 "4.7uF" C0603 4340,3740 r270 bottom
C86 "1uF" C0603 4735,4765 r315 top
C114 "1uF" C0603 5480,6650 r135 bottom
C120 "100nF" C0603 5050,6650 r180 bottom
C121 "10uF" C1206 5090,6565 r0 bottom
C122 "100nF" C0603 4900,5850 r0 bottom
C123 "100nF" C0603 4885,5750 r45 bottom
C124 "CL31A107MQHNNNE" C1206 4370,4315 r270 bottom
C126 "CL31A226KAHNNNE" C1206 4345,3985 r0 bottom
C127 "CL05B104KO5NNNC" C0402 4240,4160 r0 bottom
C129 "CL31A226KAHNNNE" C1206 4855,3855 r90 bottom
C130 "CL31A226KAHNNNE" C1206 4760,3855 r270 bottom
C131 "CL21A106KAYNNNE_C15850" C0805 4615,3995 r0 bottom
C132 "CL21A106KAYNNNE_C15850" C0805 4650,4080 r0 bottom
CARD1 "TF-115-BCP9" TF-SMD_TF-115-BCP9 5580,3545 r270 top
CN1 "PJ-327A 5JJ" AUDIO-SMD_PJ-327A5JJ 3640,6790 r180 bottom
D3 "ESD5651N" DFN1006-2L_L1.0-W0.6-ESD5651N 4305,3580 r270 bottom
D4 "ESD5651N" DFN1006-2L_L1.0-W0.6-ESD5651N 4305,3510 r90 bottom
FPC1 "BuyDisplay ER-TFT024IPS-3 FPC - 50pin 0.5mm" FPC-SMD_50P-P0.50_ER-CON50HT-1 5370,5990 r180 bottom
FPC4 "FPC-05F-30PH20" FPC-SMD_30P-P0.50_XUNPU_FPC-05F-30PH20 3715,5565 r90 bottom
H1 "HX PZ2.54-1X5P TP-YQ" HDR-SMD_5P--P2.54-V-M-S5.0_HX-PZ2.54-1X5P-TP-YQ 3590,3490 r90 top
H2 "HX PZ2.54-1X6P TP-YQ" HDR-SMD_6P-HX-PZ2.54-1X6P-TP-YQ 3985,3515 r90 top
JP1 "2P Solder UNBridge Jumper" "SOLDER BRIDGE 2P UNBRIDGED" 3485,4910 r0 bottom
JP2 "2P Solder UNBridge Jumper" "SOLDER BRIDGE 2P UNBRIDGED" 3410,4755 r270 top
JP3 "2P Solder UNBridge Jumper" "SOLDER BRIDGE 2P UNBRIDGED" 5025,5765 r90 bottom
JP4 "2P Solder UNBridge Jumper" "SOLDER BRIDGE 2P UNBRIDGED" 5150,4945 r0 bottom
JP5 "2P Solder UNBridge Jumper" "SOLDER BRIDGE 2P UNBRIDGED" 4425,4680 r315 bottom
JP6 "2P Solder UNBridge Jumper" "SOLDER BRIDGE 2P UNBRIDGED" 3960,5420 r180 bottom
JP7 "2P Solder UNBridge Jumper" "SOLDER BRIDGE 2P UNBRIDGED" 5095,6450 r180 bottom
JP8 "2P Solder UNBridge Jumper" "SOLDER BRIDGE 2P UNBRIDGED" 5295,6745 r0 bottom
JP9 "2P Solder UNBridge Jumper" "SOLDER BRIDGE 2P UNBRIDGED" 5025,6760 r270 bottom
JP13 "2P Solder UNBridge Jumper" "SOLDER BRIDGE 2P UNBRIDGED" 3865,5905 r90 bottom
JP14 "2P Solder UNBridge Jumper" "SOLDER BRIDGE 2P UNBRIDGED" 3895,5310 r0 bottom
JP15 "2P Solder UNBridge Jumper" "SOLDER BRIDGE 2P UNBRIDGED" 3825,5200 r270 bottom
JP16 "2P Solder UNBridge Jumper" "SOLDER BRIDGE 2P UNBRIDGED" 4380,5090 r0 top
JP17 "2P Solder UNBridge Jumper" "SOLDER BRIDGE 2P UNBRIDGED" 4790,5075 r180 top
JP18 "2P Solder UNBridge Jumper" "SOLDER BRIDGE 2P UNBRIDGED" 4005,5075 r180 bottom
KEY2 "K2-3.6×6.1_SMD" KEY-SMD_2P-L6.2-W3.6-LS8.0 4030,5810 r90 bottom
L2 "1575AT43A0040001E" ANT-SMD_L7.0-W2.0-R 3295,4655 r90 top
L5 "600Ω" L0805 4850,4635 r180 top
L7 "ASPI-2410-1R0N-T2" IND-SMD_L2.4-W2.4_NRH2410T 4515,4105 r270 bottom
LED1 "YLED0603R" LED0603-FD 4580,4250 r180 bottom
LED2 "YLED0603B" LED0603-FD 4080,6140 r180 bottom
LED3 "R LED" LED0603-RD_RED 4295,3835 r180 bottom
LED4 "G LED" LED0603-RD_GREEN 4215,3765 r180 bottom
LED5 "YLED0603R" LED0603-FD 4965,4960 r180 top
LED6 "TSOP4838" SENSOR-TH_TSOP4X 5135,6960 r0 bottom
LED8 "YLED0603R" LED0603-FD 5335,6645 r0 bottom
Q1 "SI2301_C727151" SOT-23-3_L2.9-W1.4-P1.91-LS2.6-BR 3705,4305 r270 bottom
Q2 "BSS138-7-F" SOT-23-3_L2.9-W1.6-P1.90-LS2.8-BR 5065,6035 r270 bottom
Q3 "2N2222AU" SOT-89-3_L4.5-W2.4-P1.50-LS4.0-BR 5645,6615 r270 bottom
R1 "10kΩ" R0603 5415,3945 r90 top
R2 "10kΩ" R0603 5480,3945 r90 top
R3 "10kΩ" R0603 5610,3945 r90 top
R4 "10kΩ" R0603 5545,3945 r90 top
R5 "10kΩ" R0603 4335,4915 r315 top
R6 "0Ω" R1206 4225,5010 r90 top
R7 "10kΩ" RES-SMD_RK10J12R0A0B 3505,6265 r270 bottom
R8 "10kΩ" R0603 3360,6605 r0 bottom
R9 "10kΩ" R0603 5455,4820 r225 bottom
R13 "10kΩ" R0603 5675,3945 r90 top
R14 "4.7kΩ" R0603 5420,4255 r225 bottom
R15 "0Ω" R1206 5570,5270 r0 bottom
R16 "4.7kΩ" R0603 5505,4235 r225 bottom
R17 "0Ω" R1206 5340,4425 r45 bottom
R18 "4.7kΩ" R0603 5700,4850 r45 bottom
R19 "0Ω" R0603 3765,3425 r270 top
R20 "0Ω" R0603 3415,3525 r270 top
R21 "1kΩ" R0603 3840,4260 r180 bottom
R22 "732kΩ" R0603 4680,3895 r90 bottom
R23 "100Ω" R0603 3715,4680 r0 top
R24 "0Ω" R0603 4185,3655 r270 bottom
R25 "100kΩ" R1206 4545,3910 r0 bottom
R26 "510Ω" R0603 4530,4185 r0 bottom
R27 "0Ω" R1206 4070,4080 r90 bottom
R28 "0Ω" R0603 4120,3655 r90 bottom
R29 "8.06kΩ" R0603 4750,4365 r180 bottom
R30 "0Ω" R1206 4230,4610 r0 top
R31 "0Ω" R1206 4600,3765 r90 bottom
R32 "1.13kΩ" R0603 4685,3570 r180 bottom
R33 "1.18kΩ" R0603 4685,3635 r180 bottom
R34 "1kΩ" R0603 4295,3905 r180 bottom
R35 "1kΩ" R0603 4185,3860 r270 bottom
R36 "5.1kΩ" R0603 4525,3420 r90 top
R37 "5.1kΩ" R0603 4630,3420 r90 top
R38 "4.7kΩ" R0603 3874.04,5565.96 r225 bottom
R39 "4.7kΩ" R0603 3920,5520 r225 bottom
R40 "100Ω" R0603 3935,6140 r180 bottom
R41 "0Ω" R1206 3535,4220 r0 bottom
R42 "33Ω" R0402 3995,4875 r180 bottom
R43 "33Ω" R0402 4355,4450 r0 bottom
R44 "22Ω" R0402 4310,4465 r0 top
R45 "33Ω" R0402 3895,4465 r180 top
R46 "22Ω" R0402 3785,4790 r270 bottom
R47 "10kΩ" R0603 5430,4295 r0 top
R49 "10kΩ" R0603 4590,4175 r180 top
R50 "10kΩ" R0603 5430,4175 r0 top
R51 "10kΩ" R0603 4610,3925 r180 top
R52 "10kΩ" R0603 4590,4295 r0 top
R53 "10kΩ" R0603 5380,4555 r180 top
R54 "0Ω" R0603 5555,4175 r0 top
R55 "0Ω" R0603 4260.34,4800 r180 top
R56 "0Ω" R0603 4260,4865 r180 top
R57 "0Ω" R0603 4015,4930 r0 bottom
R58 "0Ω" R0603 3955,4930 r180 top
R59 "22Ω" R0603 4425,4545 r315 top
R60 "10kΩ" R0603 5110,5900 r270 bottom
R61 "0Ω" R1206 5390,5210 r315 bottom
R62 "100Ω" R0603 5020,5900 r225 bottom
R63 "100Ω" R0603 5094.29,6145.71 r0 bottom
R64 "100Ω" R0603 5094.29,6210.71 r0 bottom
R65 "100Ω" R0603 5094.29,6275.71 r0 bottom
R66 "100Ω" R0603 5094.29,6345.71 r0 bottom
R67 "33Ω" R0603 5615,4890 r0 top
R68 "33Ω" R0603 5615,4830 r0 top
R69 "33Ω" R0603 5615,4770 r0 top
R70 "10kΩ" R0603 5840,4875 r0 top
R71 "470Ω" R0603 5115,4790 r0 top
R72 "470Ω" R0603 5105,4720 r0 top
R73 "10kΩ" R0603 5400,4075 r90 top
R74 "510Ω" R0603 5095,4960 r180 top
R75 "10kΩ" R0603 5125,6855 r180 bottom
R77 "1kΩ" R2512 5835,6705 r90 bottom
R80 "10kΩ" R0603 5175,6735 r180 bottom
R81 "510Ω" R0603 5200,6645 r0 bottom
R82 "10kΩ" R0603 4080,6210 r180 bottom
R83 "33Ω" R0603 4610,4785 r0 top
R84 "33Ω" R0603 4450,4895 r45 top
R85 "0Ω" R0603 3990,4990 r0 bottom
R86 "0Ω" R0603 3890,5120 r45 bottom
R87 "10kΩ" R0603 3970,4130 r0 top
R88 "10kΩ" R0603 3955,4525 r180 top
R89 "33Ω" R0603 5100,5525 r0 bottom
R90 "33Ω" R0603 5135,5440 r315 bottom
R91 "33Ω" R0603 5110,5040 r0 bottom
R92 "33Ω" R0603 5185,5110 r0 bottom
R93 "33Ω" R0603 5310,5110 r0 bottom
R94 "33Ω" R0603 5245,5170 r0 bottom
R95 "22Ω" R0402 4785,4690 r180 bottom
R96 "22Ω" R0402 5150,4480 r315 bottom
R97 "22Ω" R0402 5205,4870 r45 bottom
R98 "0Ω" R0603 5380,4685 r315 bottom
R99 "0Ω" R0603 3535,4135 r0 bottom
R100 "22Ω" R0402 4815,4760 r180 bottom
R101 "22Ω" R0402 4970,4905 r45 bottom
R102 "22Ω" R0402 4785,4640 r180 bottom
R103 "22Ω" R0402 5055,4460 r315 bottom
R104 "22Ω" R0402 4865,4510 r180 bottom
R105 "22Ω" R0402 5340,4850 r225 bottom
R106 "22Ω" R0402 5270,4500 r90 bottom
R107 "22Ω" R0402 5220,4500 r90 bottom
R108 "22Ω" R0402 5320,4770 r270 bottom
R109 "33Ω" R0402 4145,4875 r180 bottom
R111 "10kΩ" R0603 5370,4950 r0 bottom
R112 "FRC0603F7683TS" R0603 4225,4265 r180 bottom
R113 "FRC0402F1373TS" R0402 4240,4210 r180 bottom
RF1 "HC-RF-IPEX0303-01" IPEX-SMD_HC-RF-IPEX0303-01 3620,5000 r180 bottom
SCREW5 "Screw-M3" SCREW-M3 3350,3355 r180 bottom
SCREW6 "Screw-M3" SCREW-M3 5770,6980 r180 bottom
SW3 "TS-1187A-B-A-B" SW-SMD_4P-L5.1-W5.1-P3.70-LS6.5-TL_H1.5 3765,4055 r0 top
SW4 "RKJXT1F42001" SW-TH_RKJXT1F42001 5010,4235 r0 top
SW8 "TS-1187A-B-A-B" SW-SMD_4P-L5.1-W5.1-P3.70-LS6.5-TL_H1.5 4160,4455 r0 top
TP1 "Test-Point" Test-Point-0.5mm#1 5899.81,6743.23 r0 top
TP2 "Test-Point" Test-Point-0.5mm#2 3326.8,3866.02 r0 top
TP11 "Test-Point" Test-Point-0.5mm#1 5835.74,6743.56 r0 top
TP12 "Test-Point" Test-Point-0.5mm#1 5771.37,6743.32 r0 top
TP13 "Test-Point" Test-Point-0.5mm#3 5812.32,3845.26 r0 top
TP14 "Test-Point" Test-Point-0.5mm#1 5563.23,6873.01 r0 top
TP15 "Test-Point" Test-Point-0.5mm#1 5499.84,6874.63 r0 top
TP16 "Test-Point" Test-Point-0.5mm#1 5438.58,6872.74 r0 top
TP17 "Test-Point" Test-Point-0.5mm#1 5499.02,6933.64 r0 top
TP18 "Test-Point" Test-Point-0.5mm#1 5773.86,6652.73 r0 top
TP19 "Test-Point" Test-Point-0.5mm#1 5898.62,6653.47 r0 top
TP20 "Test-Point" Test-Point-0.5mm#1 5834.57,6653.32 r0 top
TP25 "Test-Point" Test-Point-0.5mm#1 5694.45,6875.44 r0 top
TP26 "Test-Point" Test-Point-0.5mm#1 5874.84,6816.87 r0 top
TP27 "Test-Point" Test-Point-0.5mm#1 5799.21,6816.24 r0 top
U2 "24MHz" OSC-SMD_4P-L2.5-W2.0-BL 4570,4485 r180 top
U3 "USB3300-EZK" QFN-32_L5.0-W5.0-P0.50-BL-EP3.4 4560,4485 r180 bottom
U5 "W25Q512JVFIQ" SOIC-16_L10.3-W7.5-P1.27-LS10.4-BL 4055,4640 r90 bottom
U6 "10kΩ" R0603 4420,3600 r0 bottom
U12 "MAX-M10S-00B" SMD-18_L10.1-W9.7-P1.10-TL_SKG09F 3485,4645 r180 bottom
U13 "TPS61023DRLR" SOT-563_L1.6-W1.2-P0.50-LS1.6-BR 4750,4005 r180 bottom
U16 "DS3231SN#" SOIC-16_L10.3-W7.5-P1.27-LS10.3-BL 5660,4545 r0 bottom
U17 "220uF" CAP-SMD_BD6.3-L6.5-W6.5-LS7.2-FD 4045,3410 r225 bottom
U18 "10kΩ" R0603 3810,4350 r90 bottom
U19 "YLED0603G" LED0603-FD 3720,4745 r0 top
U20 "10kΩ" R0603 4300,3645 r0 bottom
U26 "10kΩ" R0603 3860,4755 r180 top
U27 "AP2112K-1.8TRG1(MS)" SOT-23-5_L2.9-W1.6-P0.95-LS2.8-BR 3965,4240 r270 bottom
U28 "W958D8NBYA5I" T-PBGA-24_L8.0-W6.0-P1.00-TL_MICRON_12 5030,4745 r135 bottom
U29 "10kΩ" R0603 3415,3730 r90 top
U30 "100kΩ" R0603 3935,6395 r270 bottom
U31 "100kΩ" R0603 3865,6395 r90 bottom
U32 "S2B-PH-K(LF)(SN)" CONN-TH_S2B-PH-K-LF-SN 4005,7060 r0 bottom
U33 "BQ24075RGTR" QFN-16_L3.0-W3.0-P0.50-TL-EP1.7 4465,3710 r0 bottom
U34 "GT-USB-7010ASV" USB-C-SMD_G-SWITCH_GT-USB-7010ASV 4580,3405 r180 bottom
U37 "PCM5102APWR" TSSOP-20_L6.5-W4.4-P0.65-LS6.4-BL 5395,4880 r270 top
U38 "w" WQFN-16_L3.0-W3.0-P0.50-TL-EP1.6 4625,4925 r45 top
U40 "10kΩ" R0603 4915,4350 r90 bottom
U41 "10kΩ" R0603 4850,4420 r270 bottom
U44 "STM32H723ZGT6TR" LQFP-144_L20.0-W20.0-P0.50-LS22.0-BL 4595,5270 r135 bottom
U47 "M3X10+6CU" SMD_L4.7-W4.7-D3.0 3350,4090 r180 bottom
U48 "M3X10+6CU" SMD_L4.7-W4.7-D3.0 3350,5030 r180 bottom
U49 "M3X10+6CU" SMD_L4.7-W4.7-D3.0 5800,4090 r180 bottom
U50 "M3X10+6CU" SMD_L4.7-W4.7-D3.0 5800,5030 r180 bottom
U60 "MZ254S-11-03-10" HDR-SMD_3P-P2.54-H-M_MZ254S-11-03-10 5485,6855 r0 bottom
U61 "ESP32-WROVER-IE(16MB)" WIFI-SMD_ESP32-WROVER-E-N8R2 4560,6390 r180 bottom
U67 "TPS63020DSJR" VSON-14_L4.0-W3.0-P0.50-BL-EP_TI_DSJ 4370,4105 r0 bottom
U68 "YSMC2016S-R47M" IND-SMD_L2.0-W1.6 4855,4010 r180 bottom
U69 "10kΩ" R0603 3770,4690 r270 bottom
X2 "32.768kHz" OSC-SMD_L3.2-W1.5 4130,4850 r90 top
X3 "26MHz" OSC-SMD_4P-L5.0-W3.2-BL_SIT8103AI 3823.31,4963.31 r0 bottom

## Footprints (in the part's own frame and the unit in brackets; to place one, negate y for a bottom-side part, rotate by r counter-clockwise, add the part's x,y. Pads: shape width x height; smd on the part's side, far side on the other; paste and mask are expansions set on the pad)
ANT-SMD_L7.0-W2.0-R [mm]
  rect 1x1.8 smd: 1(3.5,0) 2(-3.5,0)
  silkscreen extent -2.86,-1.02 2.86,1.02
AUDIO-SMD_PJ-327A5JJ [mm]
  rect 3.2x2 smd: 1(3.8,4.85) 2(-3.8,3.85) 3(3.8,1.15) 4(-3.8,-3.15) 5(3.8,-4.85)
  Board Outline Layer circle w0.005: c0,3.556 r0.55
  Board Outline Layer circle w0.005: c0,-2.438 r0.55
  Board Outline Layer lines w0.254: 3.048,6.604 -3.048,6.604 ; 3.048,6.604 3.048,6.858 3.048,6.604 ; 3.048,6.604 -3.048,6.604 ; -3.048,6.604 -3.048,6.858 -3.048,6.604
  Board Outline Layer region: -0.55,3.556 -0.496,3.317 -0.343,3.126 -0.123,3.02 0.122,3.02 0.343,3.126 0.495,3.317 0.55,3.556 0.55,3.556 0.495,3.795 0.343,3.986 0.122,4.092 -0.123,4.092 -0.343,3.986 -0.496,3.795 -0.55,3.556
  Board Outline Layer region: -0.55,-2.438 -0.496,-2.677 -0.343,-2.868 -0.123,-2.975 0.122,-2.975 0.343,-2.868 0.495,-2.677 0.55,-2.438 0.55,-2.438 0.495,-2.2 0.343,-2.008 0.122,-1.902 -0.123,-1.902 -0.343,-2.008 -0.496,-2.2 -0.55,-2.438
  Multi-Layer board cut-out: -0.55,3.556 -0.496,3.317 -0.343,3.126 -0.123,3.02 0.122,3.02 0.343,3.126 0.495,3.317 0.55,3.556 0.55,3.556 0.495,3.795 0.343,3.986 0.122,4.092 -0.123,4.092 -0.343,3.986 -0.496,3.795 -0.55,3.556
  Multi-Layer board cut-out: -0.55,-2.438 -0.496,-2.677 -0.343,-2.868 -0.123,-2.975 0.122,-2.975 0.343,-2.868 0.495,-2.677 0.55,-2.438 0.55,-2.438 0.495,-2.2 0.343,-2.008 0.122,-1.902 -0.123,-1.902 -0.343,-2.008 -0.496,-2.2 -0.55,-2.438
  silkscreen extent -3,-5.65 3,8.55
BAT-SMD_BS-CR2032-8 [mm]
  rect 7x2.8 smd: 1(-11.575,0)
  rect 3.5x3.8 smd: 2(11.575,0)
  silkscreen extent -12.52,-7.85 11.52,7.85
C0402 [mm]
  rect 0.5x0.54 smd: 1(-0.42,0) 2(0.42,0)
  silkscreen extent -0.87,-0.5 0.87,0.5
C0603 [mm]
  rect 0.8x0.9 smd: 1(-0.7,0) 2(0.7,0)
  silkscreen extent -1.39,-0.71 1.39,0.71
C0805 [mm]
  rect 1.41x1.35 smd: 1(-1,0) 2(1,0)
  silkscreen extent -1.96,-0.9 1.96,0.9
C1206 [mm]
  rect 1.485x1.728 smd: 1(-1.593,0) 2(1.593,0)
  silkscreen extent -2.56,-1.09 2.56,1.09
CAP-SMD_BD6.3-L6.5-W6.5-LS7.2-FD [mm]
  rect 3.5x1.2 smd: 1(-2.67,0) 2(2.67,0)
  silkscreen extent -3.3,-3.3 3.3,3.3
CONN-TH_S2B-PH-K-LF-SN [mm]
  rect 1.5x1.5 hole 0.9: 1(1,0)
  round 1.5 hole 0.9: 2(-1,0)
  silkscreen extent -3.01,-1.35 3,6.25
DFN1006-2L_L1.0-W0.6-ESD5651N [mm]
  rect 0.4x0.6 smd: 1(-0.4,0) 2(0.4,0)
  silkscreen extent -0.76,-0.42 0.76,0.42
FPC-SMD_30P-P0.50_XUNPU_FPC-05F-30PH20 [mm]
  rect 0.3x1.25 smd: 1(-7.25,1.537) 2(-6.75,1.537) 3(-6.25,1.537) 4(-5.75,1.537) 5(-5.25,1.537) 6(-4.75,1.537) 7(-4.25,1.537) 8(-3.75,1.537) 9(-3.25,1.537) 10(-2.75,1.537) 11(-2.25,1.537) 12(-1.75,1.537) 13(-1.25,1.537) 14(-0.75,1.537) 15(-0.25,1.537) 16(0.25,1.537) 17(0.75,1.537) 18(1.25,1.537) 19(1.75,1.537) 20(2.25,1.537) 21(2.75,1.537) 22(3.25,1.537) 23(3.75,1.537) 24(4.25,1.537) 25(4.75,1.537) 26(5.25,1.537) 27(5.75,1.537) 28(6.25,1.537) 29(6.75,1.537) 30(7.25,1.537)
  rect 2x2.5 smd: 31(8.94,-1.537) 32(-8.94,-1.537)
  silkscreen extent -9.7,-4.15 9.7,1.53
FPC-SMD_50P-P0.50_ER-CON50HT-1 [mm]
  rect 1.25x0.3 smd: 1(2.938,12.437) 2(2.938,11.937) 3(2.938,11.437) 4(2.938,10.937) 5(2.938,10.437) 6(2.938,9.937) 7(2.938,9.437) 8(2.938,8.937) 9(2.938,8.437) 10(2.938,7.937) 11(2.938,7.437) 12(2.938,6.937) 13(2.938,6.437) 14(2.938,5.937) 15(2.938,5.437) 16(2.938,4.937) 17(2.938,4.437) 18(2.938,3.937) 19(2.938,3.437) 20(2.938,2.937) 21(2.938,2.437) 22(2.938,1.937) 23(2.938,1.437) 24(2.938,0.937) 25(2.938,0.437) 26(2.938,-0.063) 27(2.938,-0.563) 28(2.938,-1.063) 29(2.938,-1.563) 30(2.938,-2.063) 31(2.938,-2.563) 32(2.938,-3.063) 33(2.938,-3.563) 34(2.938,-4.063) 35(2.938,-4.563) 36(2.938,-5.063) 37(2.938,-5.563) 38(2.938,-6.063) 39(2.938,-6.563) 40(2.938,-7.063) 41(2.938,-7.563) 42(2.939,-8.063) 43(2.939,-8.563) 44(2.939,-9.062) 45(2.939,-9.562) 46(2.939,-10.062) 47(2.94,-10.562) 48(2.94,-11.062) 49(2.94,-11.562) 50(2.94,-12.061)
  rect 3x2 smd: 51(0.612,13.977) 52(0.613,-13.603)
  silkscreen extent -3.56,-15.14 3.16,15.51
HDR-SMD_3P-P2.54-H-M_MZ254S-11-03-10 [mm]
  rect 1x2.6 smd: 1(-2.54,0) 2(0,0) 3(2.54,0)
  silkscreen extent -3.86,-9.7 3.81,0.56
HDR-SMD_5P--P2.54-V-M-S5.0_HX-PZ2.54-1X5P-TP-YQ [mm]
  rect 1.02x3.02 smd: 1(-5.08,1.69) 2(-2.54,-1.69) 3(0,1.69) 4(2.54,-1.69) 5(5.08,1.69)
  silkscreen extent -6.6,-1.25 6.35,2.4
HDR-SMD_6P-HX-PZ2.54-1X6P-TP-YQ [mm]
  rect 1.02x3.02 smd: 1(-6.35,1.69) 2(-3.81,-1.69) 3(-1.27,1.69) 4(1.27,-1.69) 5(3.81,1.69) 6(6.35,-1.69)
  silkscreen extent -7.87,-1.25 7.62,2.4
IND-SMD_L2.0-W1.6 [mm]
  rect 1x1.72 smd: 1(0.828,0) 2(-0.828,0)
  silkscreen extent -1.14,-1.02 1.14,1.02
IND-SMD_L2.4-W2.4_NRH2410T [mm]
  rect 0.7x2 smd: 1(-0.725,0) 2(0.725,0)
  silkscreen extent -1.2,-1.2 1.2,1.2
IPEX-SMD_HC-RF-IPEX0303-01 [mm]
  rect 1x1.05 smd: 1(0,-1.5) 4(0,1.5)
  rect 1.05x2.2 smd: 2(1.475,0) 3(-1.475,0)
  silkscreen extent -1.45,-1.45 1.45,1.45
KEY-SMD_2P-L6.2-W3.6-LS8.0 [mm]
  rect 1.4x1.5 smd: 1(-3.8,0) 2(3.8,0)
  silkscreen extent -3.1,-1.8 3.1,1.8
L0805 [mil]
  rect 44.59x54.21 smd: 1(-38.04,0) 2(38.04,0)
  silkscreen extent -77,-40 73,40
LED0603-FD [mm]
  rect 0.9x1 smd: 1(-0.85,0) 2(0.85,0)
  silkscreen extent -1.55,-0.75 1.75,0.75
LED0603-RD_GREEN [mm]
  rect 0.8x0.8 smd: 1(-0.8,-0.004) 2(0.799,0.004)
  silkscreen extent -1.49,-0.75 1.39,0.76
LED0603-RD_RED [mm]
  rect 0.8x0.8 smd: 1(-0.749,-0.004) 2(0.749,0.004)
  silkscreen extent -1.49,-0.75 1.39,0.76
LQFP-144_L20.0-W20.0-P0.50-LS22.0-BL [mm]
  oval 0.28x2 smd: 1(-8.75,-10.8) 2(-8.25,-10.8) 3(-7.75,-10.8) 4(-7.25,-10.8) 5(-6.75,-10.8) 6(-6.25,-10.8) 7(-5.75,-10.8) 8(-5.25,-10.8) 9(-4.75,-10.8) 10(-4.25,-10.8) 11(-3.75,-10.8) 12(-3.25,-10.8) 13(-2.75,-10.8) 14(-2.25,-10.8) 15(-1.75,-10.8) 16(-1.25,-10.8) 17(-0.75,-10.8) 18(-0.25,-10.8) 19(0.25,-10.8) 20(0.75,-10.8) 21(1.25,-10.8) 22(1.75,-10.8) 23(2.25,-10.8) 24(2.75,-10.8) 25(3.25,-10.8) 26(3.75,-10.8) 27(4.25,-10.8) 28(4.75,-10.8) 29(5.25,-10.8) 30(5.75,-10.8) 31(6.25,-10.8) 32(6.75,-10.8) 33(7.25,-10.8) 34(7.75,-10.8) 35(8.25,-10.8) 36(8.75,-10.8) 73(8.75,10.8) 74(8.25,10.8) 75(7.75,10.8) 76(7.25,10.8) 77(6.75,10.8) 78(6.25,10.8) 79(5.75,10.8) 80(5.25,10.8) 81(4.75,10.8) 82(4.25,10.8) 83(3.75,10.8) 84(3.25,10.8) 85(2.75,10.8) 86(2.25,10.8) 87(1.75,10.8) 88(1.25,10.8) 89(0.75,10.8) 90(0.25,10.8) 91(-0.25,10.8) 92(-0.75,10.8) 93(-1.25,10.8) 94(-1.75,10.8) 95(-2.25,10.8) 96(-2.75,10.8) 97(-3.25,10.8) 98(-3.75,10.8) 99(-4.25,10.8) 100(-4.75,10.8) 101(-5.25,10.8) 102(-5.75,10.8) 103(-6.25,10.8) 104(-6.75,10.8) 105(-7.25,10.8) 106(-7.75,10.8) 107(-8.25,10.8) 108(-8.75,10.8)
  oval 2x0.28 smd: 37(10.8,-8.75) 38(10.8,-8.25) 39(10.8,-7.75) 40(10.8,-7.25) 41(10.8,-6.75) 42(10.8,-6.25) 43(10.8,-5.75) 44(10.8,-5.25) 45(10.8,-4.75) 46(10.8,-4.25) 47(10.8,-3.75) 48(10.8,-3.25) 49(10.8,-2.75) 50(10.8,-2.25) 51(10.8,-1.75) 52(10.8,-1.25) 53(10.8,-0.75) 54(10.8,-0.25) 55(10.8,0.25) 56(10.8,0.75) 57(10.8,1.25) 58(10.8,1.75) 59(10.8,2.25) 60(10.8,2.75) 61(10.8,3.25) 62(10.8,3.75) 63(10.8,4.25) 64(10.8,4.75) 65(10.8,5.25) 66(10.8,5.75) 67(10.8,6.25) 68(10.8,6.75) 69(10.8,7.25) 70(10.8,7.75) 71(10.8,8.25) 72(10.8,8.75) 109(-10.8,8.75) 110(-10.8,8.25) 111(-10.8,7.75) 112(-10.8,7.25) 113(-10.8,6.75) 114(-10.8,6.25) 115(-10.8,5.75) 116(-10.8,5.25) 117(-10.8,4.75) 118(-10.8,4.25) 119(-10.8,3.75) 120(-10.8,3.25) 121(-10.8,2.75) 122(-10.8,2.25) 123(-10.8,1.75) 124(-10.8,1.25) 125(-10.8,0.75) 126(-10.8,0.25) 127(-10.8,-0.25) 128(-10.8,-0.75) 129(-10.8,-1.25) 130(-10.8,-1.75) 131(-10.8,-2.25) 132(-10.8,-2.75) 133(-10.8,-3.25) 134(-10.8,-3.75) 135(-10.8,-4.25) 136(-10.8,-4.75) 137(-10.8,-5.25) 138(-10.8,-5.75) 139(-10.8,-6.25) 140(-10.8,-6.75) 141(-10.8,-7.25) 142(-10.8,-7.75) 143(-10.8,-8.25) 144(-10.8,-8.75)
  silkscreen extent -10.41,-11.25 10.08,10.08
OSC-SMD_4P-L2.5-W2.0-BL [mm]
  rect 1.2x1.1 smd: 1(-0.95,-0.75) 2(0.95,-0.75) 3(0.95,0.75) 4(-0.95,0.75)
  silkscreen extent -2.01,-1.76 1.78,1.53
OSC-SMD_4P-L5.0-W3.2-BL_SIT8103AI [mm]
  rect 1.6x1.6 smd: 1(-1.27,-1.1) 2(1.27,-1.1) 3(1.27,1.1) 4(-1.27,1.1)
  silkscreen extent -2.54,-2.69 2.54,1.52
OSC-SMD_L3.2-W1.5 [mm]
  rect 0.85x1.7 smd: 1(-1.155,0) 2(1.155,0)
  silkscreen extent -2.03,-1.08 2.03,1.08
QFN-16_L3.0-W3.0-P0.50-TL-EP1.7 [mm]
  oval 0.85x0.28 smd: 1(-1.5,0.75) 2(-1.5,0.25) 3(-1.5,-0.25) 4(-1.5,-0.75) 9(1.5,-0.75) 10(1.5,-0.25) 11(1.5,0.25) 12(1.5,0.75)
  oval 0.28x0.85 smd: 5(-0.75,-1.5) 6(-0.25,-1.5) 7(0.25,-1.5) 8(0.75,-1.5) 13(0.75,1.5) 14(0.25,1.5) 15(-0.25,1.5) 16(-0.75,1.5)
  round 0.34 smd: 17(0,0)
  Top Layer region: 0.85,0.85 0.85,-0.85 -0.85,-0.85 -0.85,0.425 -0.425,0.85
  silkscreen extent -2.38,-1.72 1.72,1.73
QFN-32_L5.0-W5.0-P0.50-BL-EP3.4 [mm]
  rect 0.28x0.8 smd: 1(-1.75,-2.5) 2(-1.251,-2.5) 3(-0.751,-2.5) 4(-0.251,-2.5) 5(0.249,-2.5) 6(0.749,-2.5) 7(1.249,-2.5) 8(1.749,-2.5) 17(1.752,2.5) 18(1.251,2.5) 19(0.752,2.5) 20(0.251,2.5) 21(-0.248,2.5) 22(-0.749,2.5) 23(-1.248,2.5) 24(-1.749,2.5)
  rect 0.8x0.28 smd: 9(2.5,-1.748) 10(2.5,-1.248) 11(2.5,-0.748) 12(2.5,-0.248) 13(2.5,0.252) 14(2.5,0.752) 15(2.5,1.252) 16(2.5,1.752) 25(-2.5,1.75) 26(-2.5,1.25) 27(-2.5,0.75) 28(-2.5,0.25) 29(-2.5,-0.25) 30(-2.5,-0.75) 31(-2.5,-1.25) 32(-2.5,-1.75)
  rect 3.4x3.4 smd: 33(0,0)
  silkscreen extent -2.6,-3.12 2.6,2.6
R0402 [mm]
  rect 0.566x0.54 smd: 1(-0.433,0) 2(0.433,0)
  silkscreen extent -0.94,-0.5 0.94,0.5
R0603 [mil]
  rect 31.75x34.02 smd: 1(-29.66,0) 2(29.66,0)
  silkscreen extent -55,-26 55,26
R1206 [mil]
  rect 47.54x66.97 smd: 1(-58.22,0) 2(58.22,0)
  silkscreen extent -91,-42 91,42
R2512 [mil]
  rect 50.49x136.06 smd: 1(-120.72,0) 2(120.72,0)
  silkscreen extent -155,-77 155,77
RES-SMD_RK10J12R0A0B [mm]
  rect 1.2x1.4 smd: 1(-4,-6.6) 2(-2,-6.6) 3(4,-6.6) 4(0,-6.6) 5(2,-6.6)
  rect 2.2x1.4 smd: 6(-6.1,4.9) 6(6.1,4.9)
  oval 3.2x1.6 hole 1 slot 2.5 at 0 deg: 7(0,6.6) 7(0,-1.8)
  silkscreen extent -7.01,-5.6 7.01,9.42
SCREW-M3 [mil]
  round 126 hole 126: 1(0,0)
  silkscreen extent -105,-105 105,105
SENSOR-TH_TSOP4X [mil]
  rect 71x71 hole 40: 1(-100.32,-0.81)
  round 79 hole 40: 2(-0.6,-0.09) 3(100.3,0.81)
  silkscreen extent -148,-160 146,60
SMD-18_L10.1-W9.7-P1.10-TL_SKG09F [mm]
  rect 1.8x0.7 smd: 1(-4.8,4.4) 2(-4.8,3.3) 3(-4.8,2.2) 4(-4.8,1.1) 5(-4.8,0) 6(-4.8,-1.1) 7(-4.8,-2.2) 8(-4.8,-3.3) 9(-4.8,-4.4) 10(4.8,-4.4) 11(4.8,-3.3) 12(4.8,-2.2) 13(4.8,-1.1) 14(4.8,0) 15(4.8,1.1) 16(4.8,2.2) 17(4.8,3.3) 18(4.8,4.4)
  silkscreen extent -4.85,-5.05 4.85,5.05
SMD_L4.7-W4.7-D3.0 [mil]
  round 18.11 smd: 1(-49.21,-60.17) 1(-49.19,60.18) 1(49.21,-60.17) 1(49.21,60.17)
  Top Layer region: 3.93,62.98 3.93,94.49 6.68,94.34 9.43,94.1 12.17,93.79 14.9,93.4 17.62,92.92 20.32,92.37 23.01,91.74 25.68,91.03 28.32,90.25 30.94,89.38 33.54,88.44 36.1,87.43 38.64,86.34 41.14,85.18 43.61,83.94 46.04,82.64 48.43,81.26 50.78,79.81 53.09,78.3 55.35,76.72 57.56,75.07 59.72,73.36 61.84,71.59 63.9,69.75 65.91,67.86 67.86,65.91 69.75,63.9 71.59,61.84 73.36,59.73 75.07,57.56 76.72,55.35 78.3,53.09 79.81,50.78 81.26,48.43 82.64,46.04 83.94,43.61 85.18,41.14 86.34,38.64 87.43,36.11 88.44,33.54 89.38,30.95 90.25,28.32 91.03,25.68 91.74,23.01 92.37,20.33 92.92,17.62 93.4,14.91 93.79,12.18 94.1,9.43 94.34,6.69 94.49,3.93 62.99,3.93 62.8,6.2 62.54,8.47 62.2,10.73 61.77,12.97 61.27,15.2 60.68,17.4 60.01,19.59 59.27,21.74 58.45,23.87 57.55,25.97 56.57,28.03 55.52,30.06 54.4,32.05 53.21,33.99 51.95,35.9 50.62,37.75 49.22,39.56 47.76,41.31 46.23,43.01 44.65,44.65 43.01,46.23 41.31,47.76 39.55,49.22 37.75,50.62 35.89,51.95 33.99,53.21 32.05,54.4 30.06,55.52 28.03,56.57 25.97,57.55 23.87,58.44 21.74,59.27 19.58,60.01 17.4,60.68 15.19,61.27 12.97,61.77 10.73,62.2 8.47,62.54 6.2,62.8
  Top Layer region: 62.98,-3.93 94.49,-3.93 94.33,-6.68 94.1,-9.43 93.79,-12.17 93.39,-14.9 92.92,-17.62 92.37,-20.32 91.74,-23.01 91.03,-25.68 90.24,-28.32 89.38,-30.94 88.44,-33.54 87.43,-36.1 86.34,-38.64 85.18,-41.14 83.94,-43.61 82.64,-46.04 81.26,-48.43 79.81,-50.78 78.3,-53.08 76.72,-55.34 75.07,-57.56 73.36,-59.72 71.59,-61.84 69.75,-63.9 67.86,-65.91 65.91,-67.86 63.9,-69.75 61.84,-71.59 59.73,-73.36 57.56,-75.07 55.35,-76.72 53.09,-78.3 50.78,-79.81 48.43,-81.26 46.04,-82.63 43.61,-83.94 41.14,-85.18 38.64,-86.34 36.11,-87.43 33.54,-88.44 30.95,-89.38 28.32,-90.24 25.68,-91.03 23.01,-91.74 20.33,-92.37 17.62,-92.92 14.91,-93.39 12.17,-93.79 9.43,-94.1 6.68,-94.33 3.93,-94.49 3.93,-62.98 6.2,-62.8 8.47,-62.54 10.73,-62.2 12.97,-61.77 15.2,-61.27 17.4,-60.68 19.58,-60.01 21.74,-59.27 23.87,-58.45 25.97,-57.55 28.03,-56.57 30.06,-55.52 32.05,-54.4 33.99,-53.21 35.89,-51.95 37.75,-50.61 39.55,-49.22 41.31,-47.76 43.01,-46.23 44.65,-44.65 46.23,-43.01 47.76,-41.3 49.22,-39.55 50.61,-37.75 51.95,-35.89 53.21,-33.99 54.4,-32.05 55.52,-30.06 56.57,-28.03 57.54,-25.97 58.44,-23.87 59.26,-21.74 60.01,-19.58 60.68,-17.4 61.26,-15.19 61.77,-12.97 62.2,-10.72 62.54,-8.47 62.8,-6.2
  Top Layer region: -3.93,-62.98 -3.93,-94.49 -6.68,-94.33 -9.43,-94.1 -12.17,-93.79 -14.9,-93.39 -17.62,-92.92 -20.32,-92.37 -23.01,-91.74 -25.68,-91.03 -28.32,-90.24 -30.94,-89.38 -33.54,-88.44 -36.1,-87.43 -38.64,-86.34 -41.14,-85.18 -43.61,-83.94 -46.04,-82.63 -48.43,-81.26 -50.78,-79.81 -53.09,-78.3 -55.35,-76.72 -57.56,-75.07 -59.72,-73.36 -61.84,-71.59 -63.9,-69.75 -65.91,-67.86 -67.86,-65.91 -69.75,-63.9 -71.59,-61.84 -73.36,-59.72 -75.07,-57.56 -76.72,-55.35 -78.3,-53.09 -79.81,-50.78 -81.26,-48.43 -82.64,-46.04 -83.94,-43.61 -85.18,-41.14 -86.34,-38.64 -87.43,-36.1 -88.44,-33.54 -89.38,-30.94 -90.25,-28.32 -91.03,-25.68 -91.74,-23.01 -92.37,-20.33 -92.92,-17.62 -93.4,-14.9 -93.79,-12.17 -94.1,-9.43 -94.34,-6.68 -94.49,-3.93 -62.99,-3.93 -62.8,-6.2 -62.54,-8.47 -62.2,-10.73 -61.77,-12.97 -61.27,-15.2 -60.68,-17.4 -60.01,-19.58 -59.27,-21.74 -58.45,-23.87 -57.55,-25.97 -56.57,-28.03 -55.52,-30.06 -54.4,-32.05 -53.21,-33.99 -51.95,-35.89 -50.62,-37.75 -49.22,-39.55 -47.76,-41.31 -46.23,-43.01 -44.65,-44.65 -43.01,-46.23 -41.31,-47.76 -39.55,-49.22 -37.75,-50.61 -35.89,-51.95 -33.99,-53.21 -32.05,-54.4 -30.06,-55.52 -28.03,-56.57 -25.97,-57.54 -23.87,-58.44 -21.74,-59.26 -19.58,-60.01 -17.4,-60.68 -15.19,-61.26 -12.97,-61.77 -10.73,-62.2 -8.47,-62.54 -6.2,-62.8
  Top Layer region: -62.97,3.93 -94.47,3.93 -94.32,6.69 -94.09,9.44 -93.77,12.18 -93.38,14.91 -92.91,17.63 -92.36,20.33 -91.73,23.02 -91.02,25.68 -90.23,28.33 -89.37,30.95 -88.43,33.54 -87.41,36.11 -86.33,38.64 -85.16,41.15 -83.93,43.61 -82.62,46.05 -81.24,48.43 -79.8,50.78 -78.28,53.09 -76.7,55.35 -75.06,57.57 -73.35,59.73 -71.57,61.84 -69.74,63.91 -67.85,65.91 -65.89,67.87 -63.89,69.76 -61.83,71.59 -59.71,73.36 -57.55,75.08 -55.33,76.72 -53.07,78.3 -50.77,79.82 -48.42,81.26 -46.03,82.64 -43.59,83.95 -41.13,85.18 -38.63,86.35 -36.09,87.43 -33.53,88.45 -30.93,89.39 -28.31,90.25 -25.67,91.04 -23,91.75 -20.31,92.38 -17.61,92.93 -14.89,93.4 -12.16,93.79 -9.42,94.11 -6.67,94.34 -3.92,94.49 -3.92,62.99 -6.19,62.81 -8.46,62.55 -10.72,62.21 -12.96,61.78 -15.18,61.27 -17.39,60.69 -19.57,60.02 -21.73,59.27 -23.86,58.45 -25.96,57.55 -28.02,56.58 -30.05,55.53 -32.03,54.41 -33.98,53.21 -35.88,51.95 -37.74,50.62 -39.54,49.23 -41.29,47.76 -42.99,46.24 -44.64,44.65 -46.22,43.01 -47.74,41.31 -49.21,39.56 -50.6,37.75 -51.93,35.9 -53.19,34 -54.39,32.05 -55.51,30.06 -56.56,28.04 -57.53,25.97 -58.43,23.87 -59.25,21.74 -60,19.59 -60.66,17.41 -61.25,15.2 -61.76,12.97 -62.18,10.73 -62.53,8.48 -62.79,6.21
  Board Outline Layer circle w0.2: c0,0 r62.99
  Board Outline Layer region: -62.99,0 -56.75,-27.33 -39.27,-49.25 -14.02,-61.41 14.02,-61.41 39.27,-49.25 56.75,-27.33 62.99,0 62.99,0 56.75,27.33 39.27,49.25 14.02,61.41 -14.02,61.41 -39.27,49.25 -56.75,27.33 -62.99,0
  Multi-Layer board cut-out: -62.99,0 -56.75,-27.33 -39.27,-49.25 -14.02,-61.41 14.02,-61.41 39.27,-49.25 56.75,-27.33 62.99,0 62.99,0 56.75,27.33 39.27,49.25 14.02,61.41 -14.02,61.41 -39.27,49.25 -56.75,27.33 -62.99,0
  silkscreen extent -102,-102 102,102
SOIC-16_L10.3-W7.5-P1.27-LS10.3-BL [mil]
  oval 22.6x94.51 smd: 1(-175,-187.02) 2(-125,-187.02) 3(-75,-187.02) 4(-25,-187.02) 5(25,-187.02) 6(75,-187.02) 7(125,-187.02) 8(175,-187.02) 9(175,187.02) 10(125,187.02) 11(75,187.02) 12(25,187.02) 13(-25,187.02) 14(-75,187.02) 15(-125,187.02) 16(-175,187.02)
  silkscreen extent -210,-193 206,131
SOIC-16_L10.3-W7.5-P1.27-LS10.4-BL [mil]
  oval 22.6x94.51 smd: 1(-175,-187.02) 2(-125,-187.02) 3(-75,-187.02) 4(-25,-187.02) 5(25,-187.02) 6(75,-187.02) 7(125,-187.02) 8(175,-187.02) 9(175,187.02) 10(125.01,187.02) 11(75,187.02) 12(25.01,187.02) 13(-25,187.02) 14(-75,187.02) 15(-125,187.02) 16(-175,187.02)
  silkscreen extent -210,-193 206,131
"SOLDER BRIDGE 2P UNBRIDGED" [mm]
  round 0.2 smd: 1(-0.65,0) 2(0.75,0)
  Top Layer region: 0.25,-1 0.296,-0.999 0.342,-0.996 0.388,-0.99 0.434,-0.983 0.479,-0.973 0.524,-0.962 0.568,-0.948 0.611,-0.932 0.654,-0.915 0.696,-0.895 0.737,-0.874 0.776,-0.85 0.815,-0.825 0.853,-0.798 0.889,-0.769 0.924,-0.739 0.957,-0.707 0.989,-0.674 1.019,-0.639 1.048,-0.603 1.075,-0.565 1.1,-0.526 1.124,-0.487 1.145,-0.446 1.165,-0.404 1.182,-0.361 1.198,-0.318 1.212,-0.274 1.223,-0.229 1.233,-0.184 1.24,-0.138 1.246,-0.092 1.249,-0.046 1.25,0 1.249,0.046 1.246,0.092 1.24,0.138 1.233,0.184 1.223,0.229 1.212,0.274 1.198,0.318 1.182,0.361 1.165,0.404 1.145,0.446 1.124,0.487 1.1,0.526 1.075,0.565 1.048,0.603 1.019,0.639 0.989,0.674 0.957,0.707 0.924,0.739 0.889,0.769 0.853,0.798 0.815,0.825 0.776,0.85 0.737,0.874 0.696,0.895 0.654,0.915 0.611,0.932 0.568,0.948 0.524,0.962 0.479,0.973 0.434,0.983 0.388,0.99 0.342,0.996 0.296,0.999 0.25,1
  Top Layer region: -0.15,-1 -0.196,-0.999 -0.242,-0.996 -0.288,-0.99 -0.334,-0.983 -0.379,-0.973 -0.424,-0.962 -0.468,-0.948 -0.511,-0.932 -0.554,-0.915 -0.596,-0.895 -0.637,-0.874 -0.676,-0.85 -0.715,-0.825 -0.753,-0.798 -0.789,-0.769 -0.824,-0.739 -0.857,-0.707 -0.889,-0.674 -0.919,-0.639 -0.948,-0.603 -0.975,-0.565 -1,-0.526 -1.024,-0.487 -1.045,-0.446 -1.065,-0.404 -1.082,-0.361 -1.098,-0.318 -1.112,-0.274 -1.123,-0.229 -1.133,-0.184 -1.14,-0.138 -1.146,-0.092 -1.149,-0.046 -1.15,0 -1.149,0.046 -1.146,0.092 -1.14,0.138 -1.133,0.184 -1.123,0.229 -1.112,0.274 -1.098,0.318 -1.082,0.361 -1.065,0.404 -1.045,0.446 -1.024,0.487 -1,0.526 -0.975,0.565 -0.948,0.603 -0.919,0.639 -0.889,0.674 -0.857,0.707 -0.824,0.739 -0.789,0.769 -0.753,0.798 -0.715,0.825 -0.676,0.85 -0.637,0.874 -0.596,0.895 -0.554,0.915 -0.511,0.932 -0.468,0.948 -0.424,0.962 -0.379,0.973 -0.334,0.983 -0.288,0.99 -0.242,0.996 -0.196,0.999 -0.15,1
  silkscreen extent -1.55,-1.4 1.65,1.4
SOT-23-3_L2.9-W1.4-P1.91-LS2.6-BR [mm]
  rect 1.07x0.532 smd: 1(1.135,-0.955) 2(1.135,0.955) 3(-1.135,0)
  silkscreen extent -0.88,-1.54 0.88,1.54
SOT-23-3_L2.9-W1.6-P1.90-LS2.8-BR [mm]
  rect 1.07x0.6 smd: 1(1.235,-0.95) 2(1.235,0.95) 3(-1.235,0)
  silkscreen extent -0.88,-1.54 0.88,1.54
SOT-23-5_L2.9-W1.6-P0.95-LS2.8-BR [mm]
  rect 1x0.6 smd: 1(1.1,-0.95) 2(1.1,0) 3(1.1,0.95) 4(-1.1,0.95) 5(-1.1,-0.95)
  silkscreen extent -0.89,-1.52 2.16,1.4
SOT-89-3_L4.5-W2.4-P1.50-LS4.0-BR [mm]
  rect 1.575x0.672 smd: 1(1.356,-1.5) 3(1.356,1.5)
  round 0.38 smd: 2(-1.356,0)
  Top Layer region: -2.283,0.95 -0.429,0.95 -0.384,0.949 -0.34,0.946 -0.296,0.941 -0.252,0.933 -0.208,0.924 -0.165,0.913 -0.123,0.899 -0.081,0.884 -0.04,0.867 0,0.847 0.04,0.826 0.078,0.804 0.115,0.779 0.151,0.753 0.185,0.725 0.219,0.695 0.251,0.664 0.281,0.631 0.31,0.597 0.337,0.562 0.362,0.525 0.386,0.488 0.408,0.449 0.428,0.409 0.447,0.33 2.144,0.33 2.144,-0.33 0.447,-0.33 0.428,-0.409 0.408,-0.449 0.386,-0.488 0.362,-0.525 0.337,-0.562 0.31,-0.597 0.281,-0.631 0.251,-0.664 0.219,-0.695 0.185,-0.725 0.151,-0.753 0.115,-0.779 0.078,-0.804 0.04,-0.826 0,-0.847 -0.04,-0.867 -0.081,-0.884 -0.123,-0.899 -0.165,-0.913 -0.208,-0.924 -0.252,-0.933 -0.296,-0.941 -0.34,-0.946 -0.384,-0.949 -0.429,-0.95 -2.283,-0.95 -2.328,-0.949 -2.372,-0.946 -2.416,-0.941 -2.46,-0.933 -2.504,-0.924 -2.547,-0.913 -2.589,-0.899 -2.631,-0.884 -2.672,-0.867 -2.712,-0.847 -2.752,-0.826 -2.79,-0.804 -2.827,-0.779 -2.863,-0.753 -2.898,-0.725 -2.931,-0.695 -2.963,-0.664 -2.993,-0.631 -3.022,-0.597 -3.049,-0.562 -3.075,-0.525 -3.098,-0.488 -3.12,-0.449 -3.14,-0.409 -3.159,-0.369 -3.175,-0.327 -3.189,-0.285 -3.202,-0.242 -3.212,-0.199 -3.22,-0.155 -3.227,-0.111 -3.231,-0.067 -3.233,-0.022 -3.233,0.022 -3.231,0.067 -3.227,0.111 -3.22,0.155 -3.212,0.199 -3.202,0.242 -3.189,0.285 -3.175,0.327 -3.159,0.369 -3.14,0.409 -3.12,0.449 -3.098,0.488 -3.075,0.525 -3.049,0.562 -3.022,0.597 -2.993,0.631 -2.963,0.664 -2.931,0.695 -2.898,0.725 -2.863,0.753 -2.827,0.779 -2.79,0.804 -2.752,0.826 -2.712,0.847 -2.672,0.867 -2.631,0.884 -2.589,0.899 -2.547,0.913 -2.504,0.924 -2.46,0.933 -2.416,0.941 -2.372,0.946 -2.328,0.949
  silkscreen extent -1.65,-2.33 1,2.33
SOT-563_L1.6-W1.2-P0.50-LS1.6-BR [mm]
  rect 0.6x0.3 smd: 1(0.75,-0.5) 2(0.75,0) 3(0.75,0.5) 4(-0.75,0.5) 5(-0.75,0) 6(-0.75,-0.5)
  silkscreen extent -0.48,-0.99 0.9,0.79
SW-SMD_4P-L5.1-W5.1-P3.70-LS6.5-TL_H1.5 [mm]
  rect 1x0.75 smd: 1(-3,1.85) 2(3,1.85) 3(-3,-1.85) 4(3,-1.85)
  silkscreen extent -2.55,-2.55 2.55,2.55
SW-TH_RKJXT1F42001 [mm]
  round 1.8 hole 1.2: 5(1,-6.98) 6(-1,5.78) 7(7.8,1.5) 8(-7.8,-1.5) 9(-1.5,7.8) 10(6.86,-3.75) A(-1.5,-7.8) B(7.8,-1.5) C(1.5,7.8) D(-7.8,1.5)
  Board Outline Layer circle w0.005: c-3.8,-1.499 r0.65
  Board Outline Layer region: -3.15,-1.499 -3.214,-1.781 -3.395,-2.007 -3.655,-2.132 -3.945,-2.132 -4.205,-2.007 -4.386,-1.781 -4.45,-1.499 -4.45,-1.499 -4.386,-1.217 -4.205,-0.99 -3.945,-0.865 -3.655,-0.865 -3.395,-0.99 -3.214,-1.217 -3.15,-1.499
  Multi-Layer board cut-out: -3.15,-1.499 -3.214,-1.781 -3.395,-2.007 -3.655,-2.132 -3.945,-2.132 -4.205,-2.007 -4.386,-1.781 -4.45,-1.499 -4.45,-1.499 -4.386,-1.217 -4.205,-0.99 -3.945,-0.865 -3.655,-0.865 -3.395,-0.99 -3.214,-1.217 -3.15,-1.499
  silkscreen extent -8.5,-8.5 8.5,8.5
T-PBGA-24_L8.0-W6.0-P1.00-TL_MICRON_12 [mm]
  round 0.32 smd: A2(-1,2) A3(0,2) A4(1,2) A5(2,2) B1(-2,1) B2(-1,1) B3(0,1) B4(1,1) B5(2,1) C1(-2,0) C2(-1,0) C3(0,0) C4(1,0) C5(2,0) D1(-2,-1) D2(-1,-1) D3(0,-1) D4(1,-1) D5(2,-1) E1(-2,-2) E2(-1,-2) E3(0,-2) E4(1,-2) E5(2,-2)
  silkscreen extent -3.3,-4.08 3.08,4.3
Test-Point-0.5mm#1 [mm]
  round 1 smd: 1(0,0)
Test-Point-0.5mm#2 [mm]
  rect 1x1 smd: 1(0,0)
Test-Point-0.5mm#3 [mm]
  round 0.5 smd: 1(0,0)
TF-SMD_TF-115-BCP9 [mm]
  rect 0.7x1.6 smd: 1(2.25,5.3) 2(1.15,5.3) 3(0.05,5.3) 4(-1.05,5.3) 5(-2.15,5.3) 6(-3.25,5.3) 7(-4.35,5.3) 8(-5.45,5.3) 9(-6.55,5.3)
  rect 1.2x1.5 smd: 10(-7.75,4.3)
  rect 1.2x2.2 smd: 11(-7.75,-5.3) 13(7.75,-5.3)
  rect 1.6x1.5 smd: 12(6.85,4.3)
  Board Outline Layer circle w0.005: c-4.95,-5.69 r0.5
  Board Outline Layer circle w0.005: c3.05,-5.69 r0.5
  Board Outline Layer region: -4.95,-5.19 -4.733,-5.239 -4.559,-5.378 -4.462,-5.578 -4.462,-5.801 -4.559,-6.001 -4.733,-6.14 -4.95,-6.19 -4.95,-6.19 -5.167,-6.14 -5.341,-6.001 -5.437,-5.801 -5.437,-5.578 -5.341,-5.378 -5.167,-5.239 -4.95,-5.19
  Board Outline Layer region: 3.05,-5.19 3.267,-5.239 3.441,-5.378 3.537,-5.578 3.537,-5.801 3.441,-6.001 3.267,-6.14 3.05,-6.19 3.05,-6.19 2.833,-6.14 2.659,-6.001 2.563,-5.801 2.563,-5.578 2.659,-5.378 2.833,-5.239 3.05,-5.19
  Multi-Layer board cut-out: -4.95,-5.19 -4.733,-5.239 -4.559,-5.378 -4.462,-5.578 -4.462,-5.801 -4.559,-6.001 -4.733,-6.14 -4.95,-6.19 -4.95,-6.19 -5.167,-6.14 -5.341,-6.001 -5.437,-5.801 -5.437,-5.578 -5.341,-5.378 -5.167,-5.239 -4.95,-5.19
  Multi-Layer board cut-out: 3.05,-5.19 3.267,-5.239 3.441,-5.378 3.537,-5.578 3.537,-5.801 3.441,-6.001 3.267,-6.14 3.05,-6.19 3.05,-6.19 2.833,-6.14 2.659,-6.001 2.563,-5.801 2.563,-5.578 2.659,-5.378 2.833,-5.239 3.05,-5.19
  silkscreen extent -7.38,-9.7 7.42,4.81
TSSOP-20_L6.5-W4.4-P0.65-LS6.4-BL [mil]
  oval 14.33x68.58 smd: 1(-115.16,-113.03) 2(-89.57,-113.03) 3(-63.98,-113.03) 4(-38.39,-113.03) 5(-12.79,-113.03) 6(12.8,-113.03) 7(38.39,-113.03) 8(63.98,-113.03) 9(89.57,-113.03) 10(115.16,-113.03) 11(115.16,113.03) 12(89.57,113.03) 13(63.98,113.03) 14(38.39,113.03) 15(12.8,113.03) 16(-12.79,113.03) 17(-38.39,113.03) 18(-63.98,113.03) 19(-89.57,113.03) 20(-115.16,113.03)
  silkscreen extent -146,-119 131,70
USB-C-SMD_G-SWITCH_GT-USB-7010ASV [mm]
  oval 1x2.1 hole 0.6 slot 1.7 at 90 deg: 1(-4.32,1.78) 2(4.32,1.78)
  oval 1x1.8 hole 0.6 slot 1.4 at 90 deg: 3(4.32,-2.4) 4(-4.32,-2.4)
  rect 0.6x1.24 smd: A1B12(-3.2,2.4) A4B9(-2.4,2.4) B1A12(3.2,2.4) B4A9(2.4,2.4)
  rect 0.3x1.24 smd: A5(-1.25,2.4) A6(-0.25,2.4) A7(0.25,2.4) A8(1.25,2.4) B5(1.75,2.4) B6(0.75,2.4) B7(-0.75,2.4) B8(-1.75,2.4)
  Board Outline Layer circle w0.005: c2.89,1.27 r0.325
  Board Outline Layer circle w0.005: c-2.9,1.27 r0.325
  Board Outline Layer region: 2.565,1.27 2.597,1.129 2.687,1.016 2.818,0.953 2.962,0.953 3.093,1.016 3.183,1.129 3.215,1.27 3.215,1.27 3.183,1.411 3.093,1.524 2.962,1.587 2.818,1.587 2.687,1.524 2.597,1.411 2.565,1.27
  Board Outline Layer region: -3.225,1.27 -3.193,1.129 -3.103,1.016 -2.972,0.953 -2.828,0.953 -2.697,1.016 -2.607,1.129 -2.575,1.27 -2.575,1.27 -2.607,1.411 -2.697,1.524 -2.828,1.587 -2.972,1.587 -3.103,1.524 -3.193,1.411 -3.225,1.27
  Multi-Layer board cut-out: 2.565,1.27 2.597,1.129 2.687,1.016 2.818,0.953 2.962,0.953 3.093,1.016 3.183,1.129 3.215,1.27 3.215,1.27 3.183,1.411 3.093,1.524 2.962,1.587 2.818,1.587 2.687,1.524 2.597,1.411 2.565,1.27
  Multi-Layer board cut-out: -3.225,1.27 -3.193,1.129 -3.103,1.016 -2.972,0.953 -2.828,0.953 -2.697,1.016 -2.607,1.129 -2.575,1.27 -2.575,1.27 -2.607,1.411 -2.697,1.524 -2.828,1.587 -2.972,1.587 -3.103,1.524 -3.193,1.411 -3.225,1.27
  silkscreen extent -4.5,-5.03 4.5,0.52
VSON-14_L4.0-W3.0-P0.50-BL-EP_TI_DSJ [mm]
  rect 0.25x0.7 smd: 1(-1.5,-1.45) 2(-1,-1.45) 3(-0.5,-1.45) 4(0,-1.45) 5(0.5,-1.45) 6(1,-1.45) 7(1.5,-1.45) 8(1.5,1.45) 9(1,1.45) 10(0.5,1.45) 11(0,1.45) 12(-0.5,1.45) 13(-1,1.45) 14(-1.5,1.45)
  round 0.316 smd: 15(0,0)
  Top Layer region: -2.2,0.79 -2.2,0.59 -1.43,0.59 -1.43,0.33 -2.2,0.33 -2.2,0.13 -1.43,0.13 -1.43,-0.13 -2.2,-0.13 -2.2,-0.33 -1.43,-0.33 -1.43,-0.59 -2.2,-0.59 -2.2,-0.79 2.2,-0.79 2.2,-0.59 1.43,-0.59 1.43,-0.33 2.2,-0.33 2.2,-0.13 1.43,-0.13 1.43,0.13 2.2,0.13 2.2,0.33 1.43,0.33 1.43,0.59 2.2,0.59 2.2,0.79
  silkscreen extent -2.1,-2.23 2.1,1.6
